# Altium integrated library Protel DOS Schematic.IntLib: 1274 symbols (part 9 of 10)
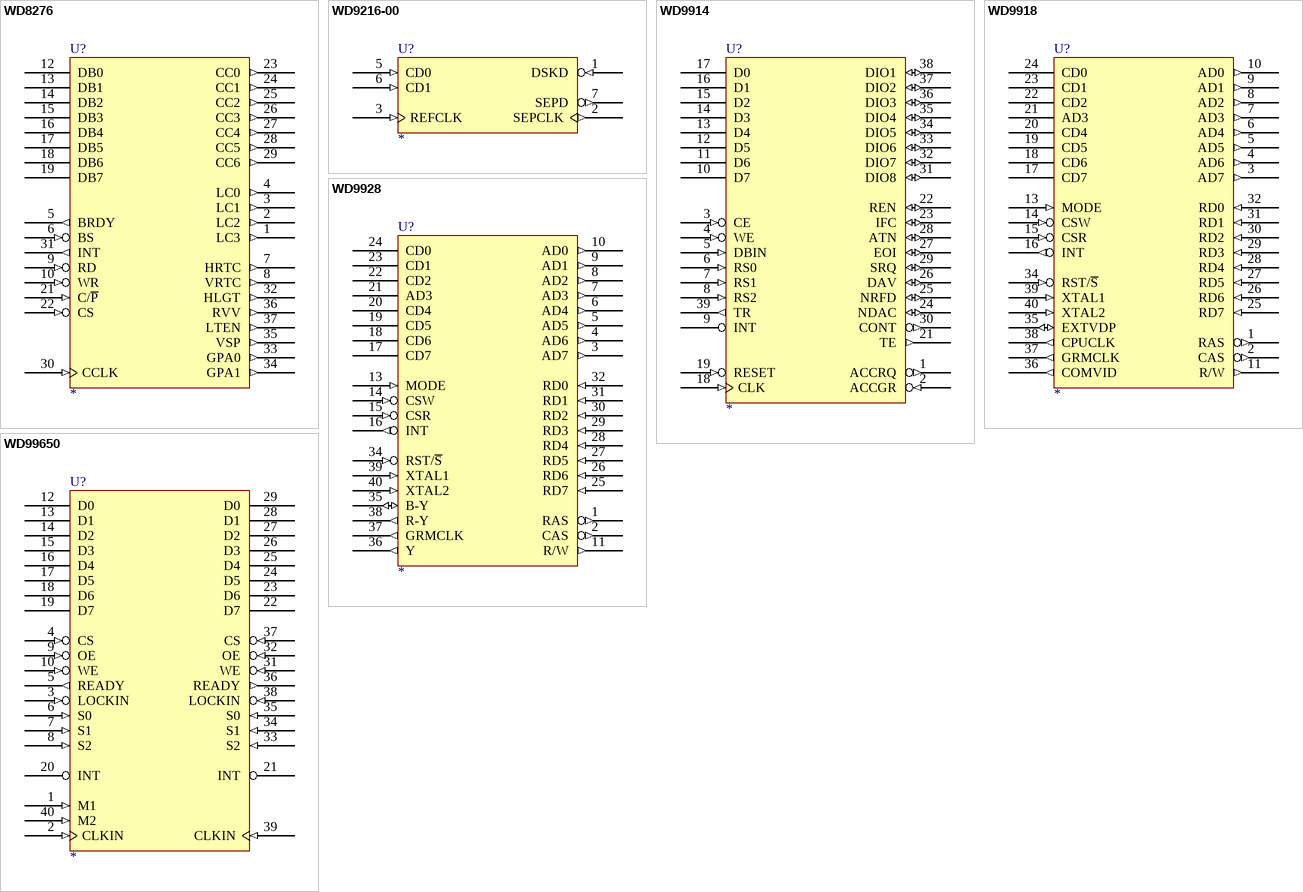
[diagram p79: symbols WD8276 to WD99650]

## WD9928
designator U?
footprint DIP-40
pins: 1 RAS (out), 2 CAS (out), 3 AD7 (out), 4 AD6 (out), 5 AD5 (out), 6 AD4 (out), 7 AD3 (out), 8 AD2 (out), 9 AD1 (out), 10 AD0 (out), 11 R/W (out), 12 GND (power) hidden to GND, 13 MODE (in), 14 CSW (in), 15 CSR (in), 16 INT (out), 17 CD7 (hiz), 18 CD6 (hiz), 19 CD5 (hiz), 20 CD4 (hiz), 21 AD3 (hiz), 22 CD2 (hiz), 23 CD1 (hiz), 24 CD0 (hiz), 25 RD7 (in), 26 RD6 (in), 27 RD5 (in), 28 RD4 (in), 29 RD3 (in), 30 RD2 (in), 31 RD1 (in), 32 RD0 (in), 33 VCC (power) hidden to VCC, 34 RST/~{S} (in), 35 B-Y (io), 36 Y (out), 37 GRMCLK (out), 38 R-Y (out), 39 XTAL1 (in), 40 XTAL2 (in)
2 alternate drawings of the same symbol

## WD99650
designator U?
footprint DIP-40
pins: 1 M1 (in), 2 CLKIN (in), 3 LOCKIN (in), 4 CS (in), 5 READY (out), 6 S0 (in), 7 S1 (in), 8 S2 (in), 9 OE (in), 10 WE (in), 11 GND (power) hidden to GND, 12 D0 (hiz), 13 D1 (hiz), 14 D2 (hiz), 15 D3 (hiz), 16 D4 (hiz), 17 D5 (hiz), 18 D6 (hiz), 19 D7 (hiz), 20 INT (oc), 21 INT (oc), 22 D7 (hiz), 23 D6 (hiz), 24 D5 (hiz), 25 D4 (hiz), 26 D3 (hiz), 27 D2 (hiz), 28 D1 (hiz), 29 D0 (hiz), 30 VCC (power) hidden to VCC, 31 WE (in), 32 OE (in), 33 S2 (in), 34 S1 (in), 35 S0 (in), 36 READY (out), 37 CS (in), 38 LOCKIN (in), 39 CLKIN (in), 40 M2 (in)
2 alternate drawings of the same symbol


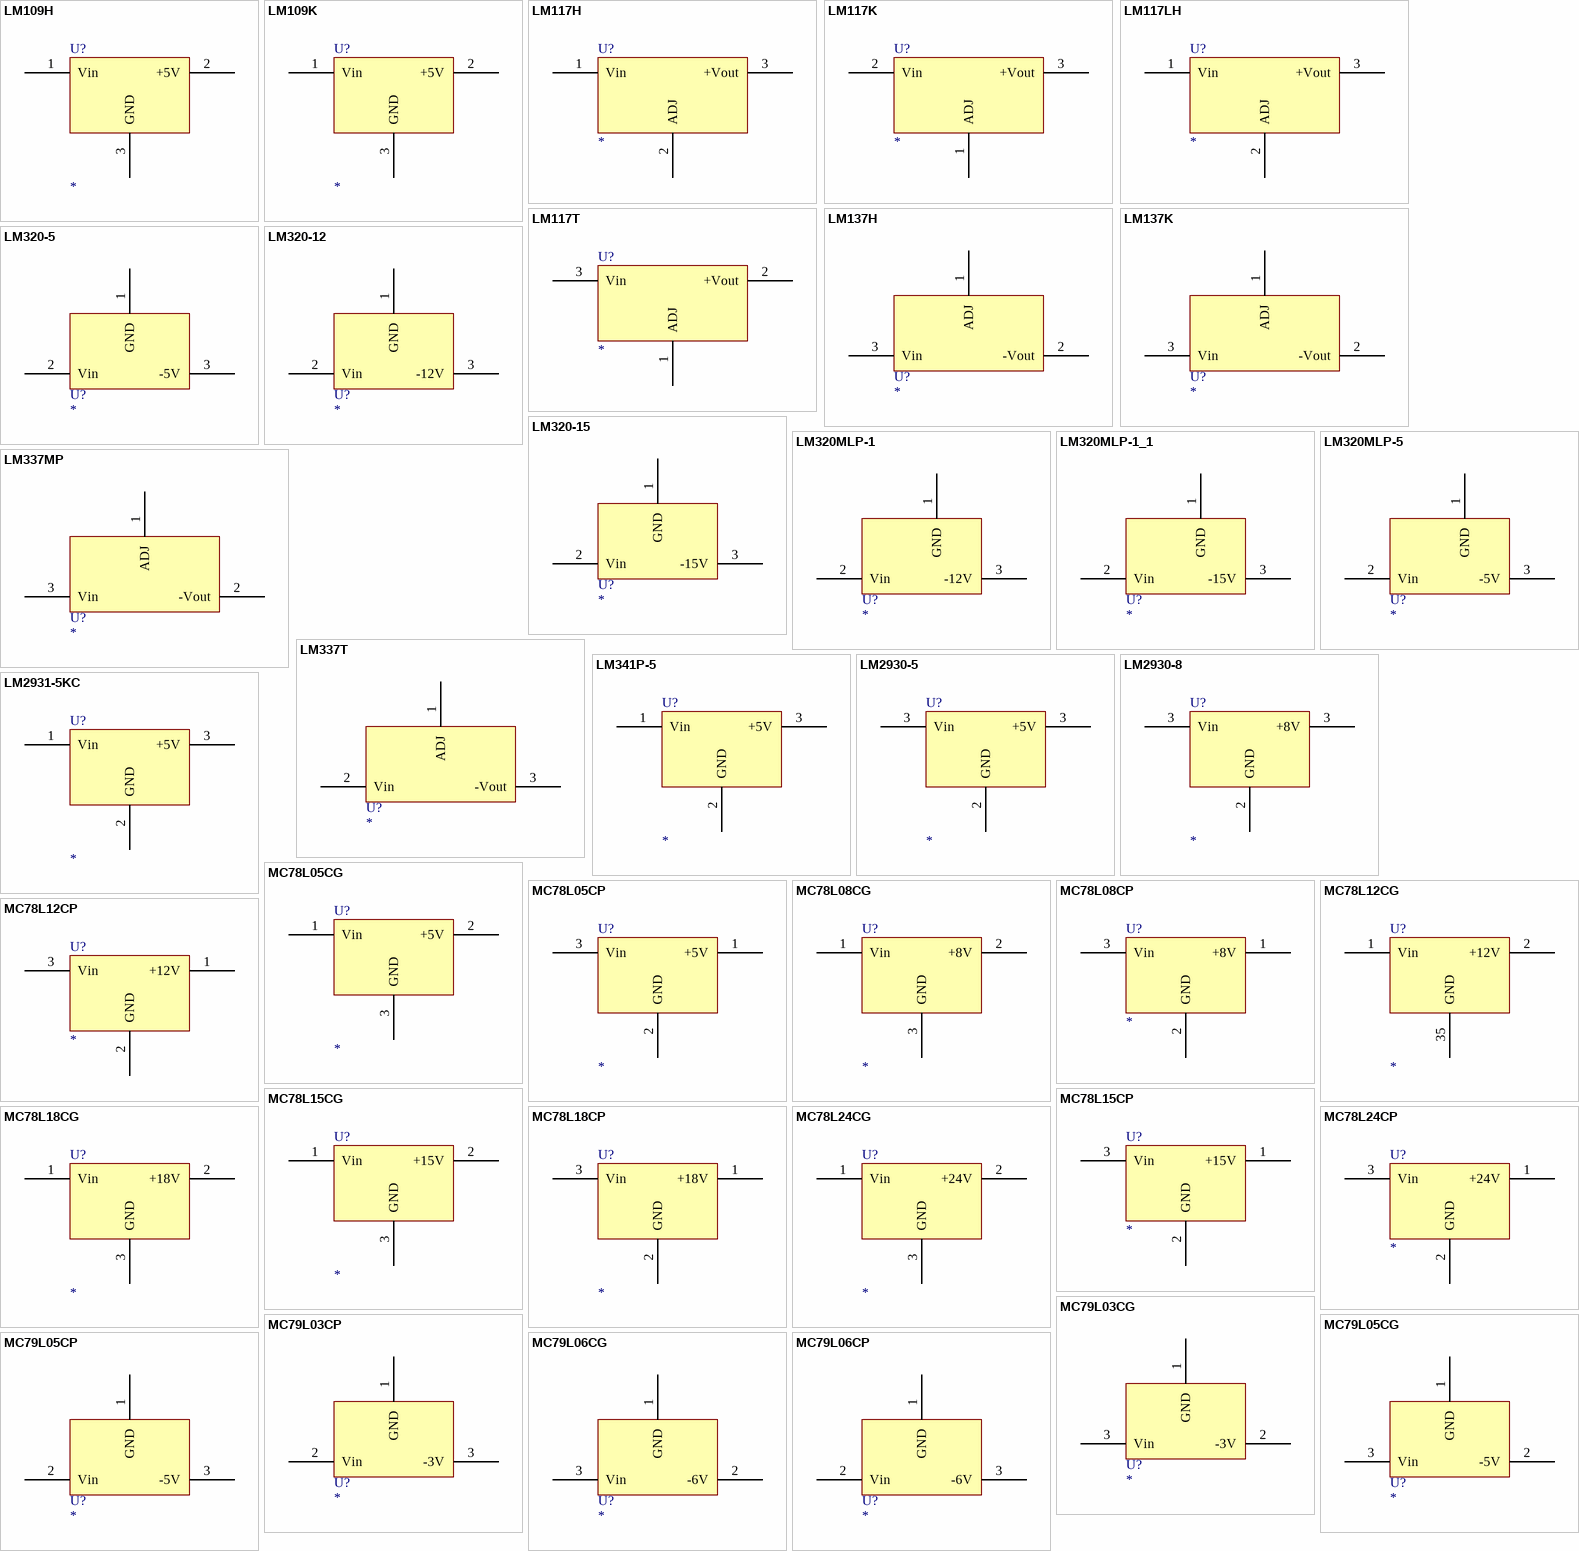
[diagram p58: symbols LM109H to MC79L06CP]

## LM109H
designator U?
footprint TO-39
pins: 1 Vin, 2 +5V, 3 GND
2 alternate drawings of the same symbol

## LM109K
designator U?
footprint TO-3
pins: 1 Vin, 2 +5V, 3 GND
2 alternate drawings of the same symbol

## LM117H
designator U?
footprint TO39
pins: 1 Vin, 2 ADJ, 3 +Vout
2 alternate drawings of the same symbol

## LM117K
designator U?
footprint TO3
footprint TO220V
footprint TO220H
footprint TO252-3L (Footprint not found)
pins: 1 ADJ, 2 Vin, 3 +Vout
2 alternate drawings of the same symbol

## LM117LH
designator U?
footprint TO39
pins: 1 Vin, 2 ADJ, 3 +Vout
2 alternate drawings of the same symbol

## LM117T
designator U?
footprint TO220H
footprint TO220V
footprint TO252-3L (Footprint not found)
pins: 1 ADJ, 2 +Vout, 3 Vin
2 alternate drawings of the same symbol

## LM137H
designator U?
footprint TO-39
pins: 1 ADJ, 2 -Vout, 3 Vin
2 alternate drawings of the same symbol

## LM137K
designator U?
footprint TO-3
pins: 1 ADJ, 2 -Vout, 3 Vin
2 alternate drawings of the same symbol

## LM320-5
designator U?
footprint TO220H
pins: 1 GND, 2 Vin, 3 -5V
2 alternate drawings of the same symbol

## LM320-12
designator U?
footprint TO220H
pins: 1 GND, 2 Vin, 3 -12V
2 alternate drawings of the same symbol

## LM320-15
designator U?
footprint TO220H
pins: 1 GND, 2 Vin, 3 -15V
2 alternate drawings of the same symbol

## LM320MLP-1
designator U?
footprint TO202H
pins: 1 GND, 2 Vin, 3 -12V
2 alternate drawings of the same symbol

## LM320MLP-1_1
designator U?
footprint TO202H
pins: 1 GND, 2 Vin, 3 -15V
2 alternate drawings of the same symbol

## LM320MLP-5
designator U?
footprint TO202H
pins: 1 GND, 2 Vin, 3 -5V
2 alternate drawings of the same symbol

## LM337MP
designator U?
footprint TO202H
pins: 1 ADJ, 2 -Vout, 3 Vin
2 alternate drawings of the same symbol

## LM337T
designator U?
footprint TO220H
footprint TO220V
pins: 1 ADJ, 2 Vin, 3 -Vout
2 alternate drawings of the same symbol

## LM341P-5
designator U?
footprint TO202H
pins: 1 Vin, 2 GND, 3 +5V
2 alternate drawings of the same symbol

## LM2930-5
designator U?
footprint TO220H
pins: 2 GND, 3 Vin, 3 +5V
2 alternate drawings of the same symbol

## LM2930-8
designator U?
footprint TO220H
pins: 2 GND, 3 Vin, 3 +8V
2 alternate drawings of the same symbol

## LM2931-5KC
designator U?
footprint TO220H
pins: 1 Vin, 2 GND, 3 +5V
2 alternate drawings of the same symbol

## MC78L05CG
designator U?
footprint TO-39
pins: 1 Vin, 2 +5V, 3 GND
2 alternate drawings of the same symbol

## MC78L05CP
designator U?
footprint TO-92A
pins: 1 +5V, 2 GND, 3 Vin
2 alternate drawings of the same symbol

## MC78L08CG
designator U?
footprint TO-39
pins: 1 Vin, 2 +8V, 3 GND
2 alternate drawings of the same symbol

## MC78L08CP
designator U?
footprint TO-92A
pins: 1 +8V, 2 GND, 3 Vin
2 alternate drawings of the same symbol

## MC78L12CG
designator U?
footprint TO-39
pins: 1 Vin, 2 +12V, 35 GND
2 alternate drawings of the same symbol

## MC78L12CP
designator U?
footprint TO-92A
pins: 1 +12V, 2 GND, 3 Vin
2 alternate drawings of the same symbol

## MC78L15CG
designator U?
footprint TO-39
pins: 1 Vin, 2 +15V, 3 GND
2 alternate drawings of the same symbol

## MC78L15CP
designator U?
footprint TO-92A
pins: 1 +15V, 2 GND, 3 Vin
2 alternate drawings of the same symbol

## MC78L18CG
designator U?
footprint TO-39
pins: 1 Vin, 2 +18V, 3 GND
2 alternate drawings of the same symbol

## MC78L18CP
designator U?
footprint TO-92A
pins: 1 +18V, 2 GND, 3 Vin
2 alternate drawings of the same symbol

## MC78L24CG
designator U?
footprint TO-39
pins: 1 Vin, 2 +24V, 3 GND
2 alternate drawings of the same symbol

## MC78L24CP
designator U?
footprint TO-92A
pins: 1 +24V, 2 GND, 3 Vin
2 alternate drawings of the same symbol

## MC79L03CG
designator U?
footprint TO-39
pins: 1 GND, 2 -3V, 3 Vin
2 alternate drawings of the same symbol

## MC79L03CP
designator U?
footprint TO-92A
pins: 1 GND, 2 Vin, 3 -3V
2 alternate drawings of the same symbol

## MC79L05CG
designator U?
footprint TO-39
pins: 1 GND, 2 -5V, 3 Vin
2 alternate drawings of the same symbol

## MC79L05CP
designator U?
footprint TO-92A
pins: 1 GND, 2 Vin, 3 -5V
2 alternate drawings of the same symbol

## MC79L06CG
designator U?
footprint TO-39
pins: 1 GND, 2 -6V, 3 Vin
2 alternate drawings of the same symbol

## MC79L06CP
designator U?
footprint TO-92A
pins: 1 GND, 2 Vin, 3 -6V
2 alternate drawings of the same symbol

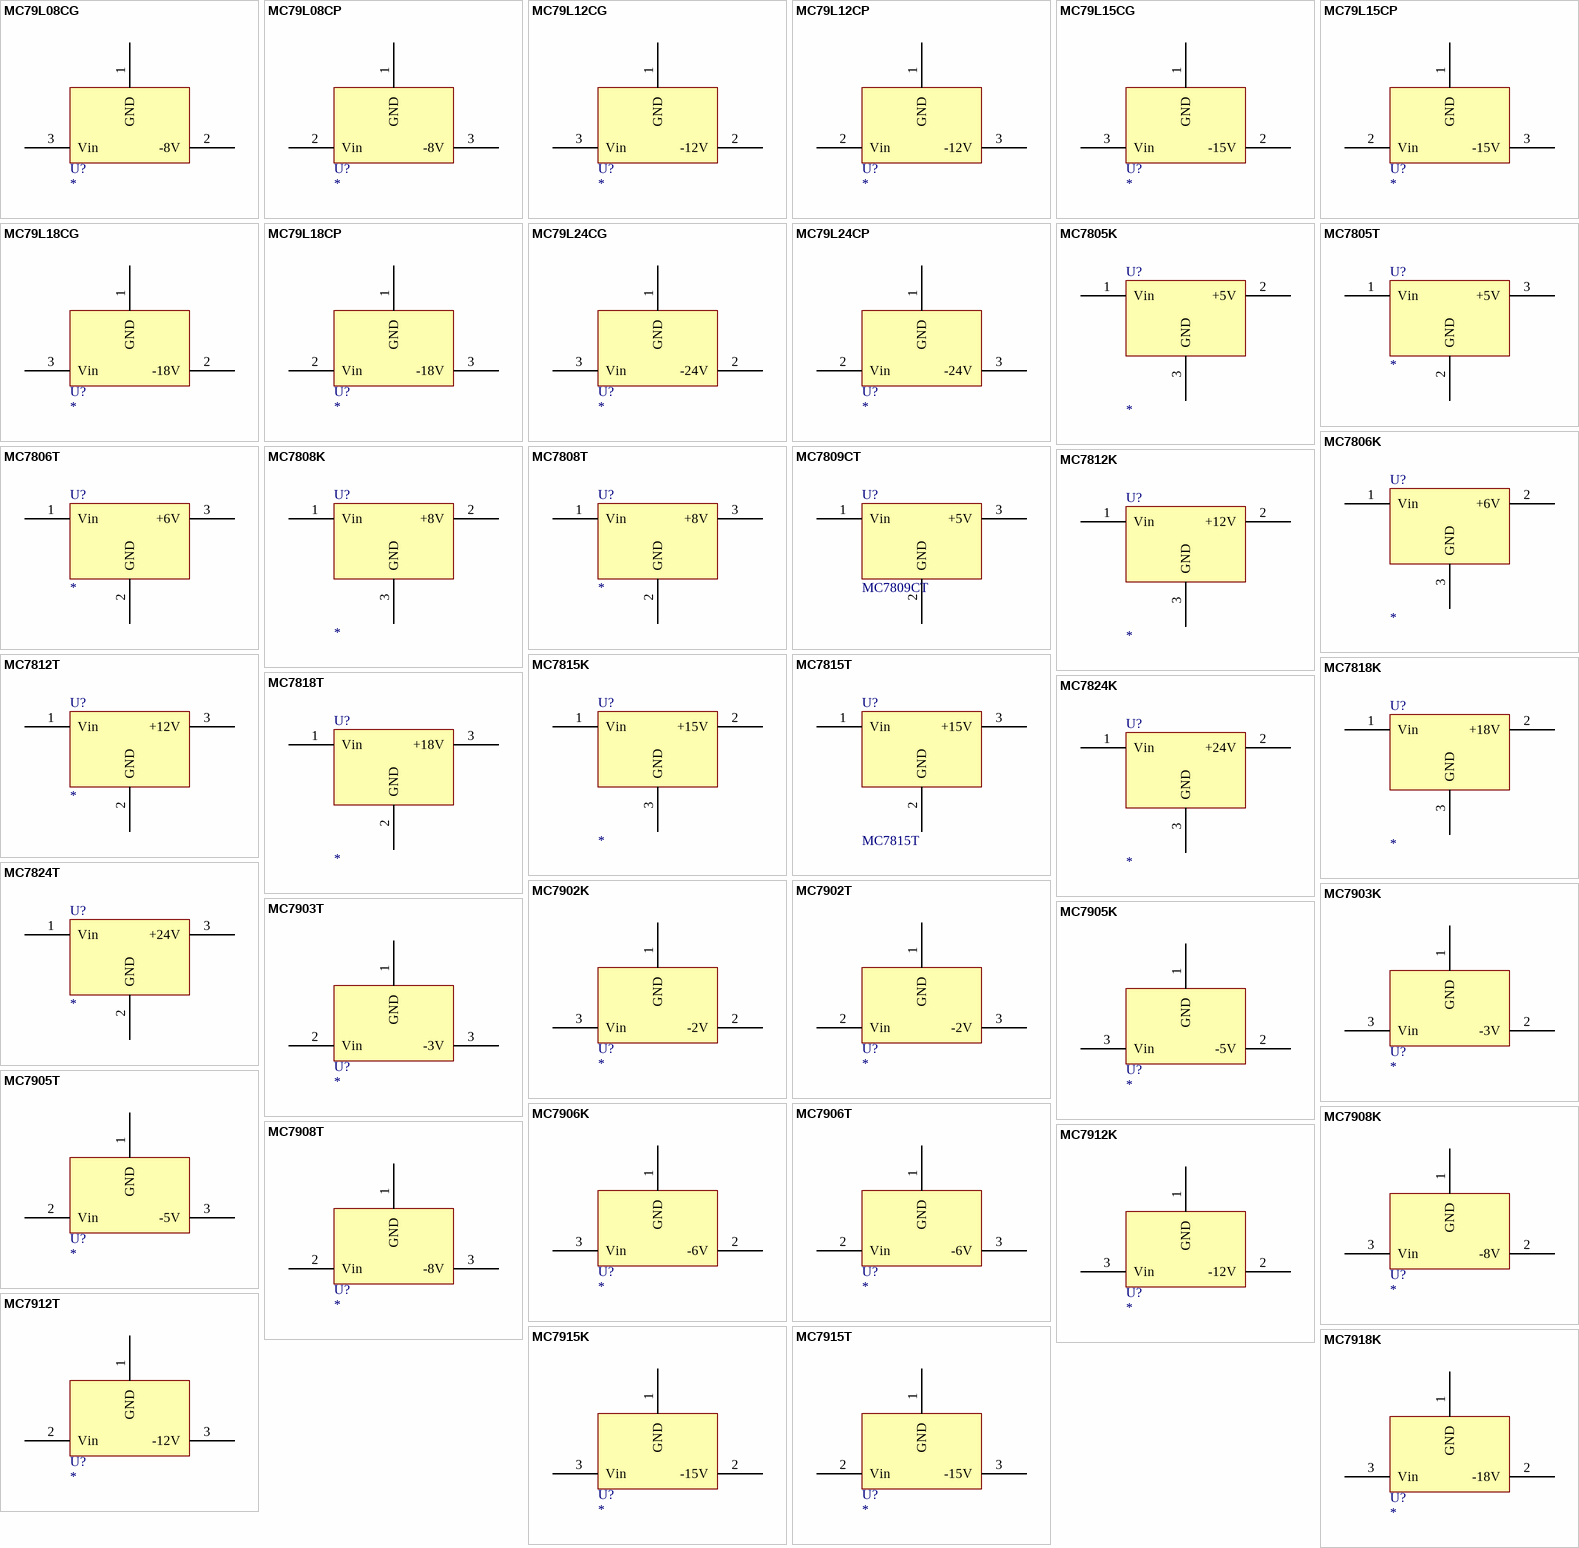
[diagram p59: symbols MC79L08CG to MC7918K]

## MC79L08CG
designator U?
footprint TO-39
pins: 1 GND, 2 -8V, 3 Vin
2 alternate drawings of the same symbol

## MC79L08CP
designator U?
footprint TO-92A
pins: 1 GND, 2 Vin, 3 -8V
2 alternate drawings of the same symbol

## MC79L12CG
designator U?
footprint TO-39
pins: 1 GND, 2 -12V, 3 Vin
2 alternate drawings of the same symbol

## MC79L12CP
designator U?
footprint TO-92A
pins: 1 GND, 2 Vin, 3 -12V
2 alternate drawings of the same symbol

## MC79L15CG
designator U?
footprint TO-39
pins: 1 GND, 2 -15V, 3 Vin
2 alternate drawings of the same symbol

## MC79L15CP
designator U?
footprint TO-92A
pins: 1 GND, 2 Vin, 3 -15V
2 alternate drawings of the same symbol

## MC79L18CG
designator U?
footprint TO-39
pins: 1 GND, 2 -18V, 3 Vin
2 alternate drawings of the same symbol

## MC79L18CP
designator U?
footprint TO-92A
pins: 1 GND, 2 Vin, 3 -18V
2 alternate drawings of the same symbol

## MC79L24CG
designator U?
footprint TO-39
pins: 1 GND, 2 -24V, 3 Vin
2 alternate drawings of the same symbol

## MC79L24CP
designator U?
footprint TO-92A
pins: 1 GND, 2 Vin, 3 -24V
2 alternate drawings of the same symbol

## MC7805K
designator U?
footprint TO-3
pins: 1 Vin, 2 +5V, 3 GND
2 alternate drawings of the same symbol

## MC7805T
designator U?
footprint TO220H
footprint TO220V
footprint TO257H
pins: 1 Vin, 2 GND, 3 +5V
2 alternate drawings of the same symbol

## MC7806K
designator U?
footprint TO-3
pins: 1 Vin, 2 +6V, 3 GND
2 alternate drawings of the same symbol

## MC7806T
designator U?
footprint TO220H
footprint TO220V
pins: 1 Vin, 2 GND, 3 +6V
2 alternate drawings of the same symbol

## MC7808K
designator U?
footprint TO-3
pins: 1 Vin, 2 +8V, 3 GND
2 alternate drawings of the same symbol

## MC7808T
designator U?
footprint TO220H
footprint TO220V
pins: 1 Vin, 2 GND, 3 +8V
2 alternate drawings of the same symbol

## MC7809CT
designator U?
footprint TO220H
footprint TO220V
footprint TO257H
pins: 1 Vin, 2 GND, 3 +5V
2 alternate drawings of the same symbol

## MC7812K
designator U?
footprint TO-3
pins: 1 Vin, 2 +12V, 3 GND
2 alternate drawings of the same symbol

## MC7812T
designator U?
footprint TO220H
footprint TO220V
pins: 1 Vin, 2 GND, 3 +12V
2 alternate drawings of the same symbol

## MC7815K
designator U?
footprint TO-3
pins: 1 Vin, 2 +15V, 3 GND
2 alternate drawings of the same symbol

## MC7815T
designator U?
footprint TO220H
footprint TO220V
pins: 1 Vin, 2 GND, 3 +15V
2 alternate drawings of the same symbol

## MC7818K
designator U?
footprint TO-3
pins: 1 Vin, 2 +18V, 3 GND
2 alternate drawings of the same symbol

## MC7818T
designator U?
footprint TO220H
pins: 1 Vin, 2 GND, 3 +18V
2 alternate drawings of the same symbol

## MC7824K
designator U?
footprint TO-3
pins: 1 Vin, 2 +24V, 3 GND
2 alternate drawings of the same symbol

## MC7824T
designator U?
footprint TO220H
footprint TO220V
pins: 1 Vin, 2 GND, 3 +24V
2 alternate drawings of the same symbol

## MC7902K
designator U?
footprint TO-3
pins: 1 GND, 2 -2V, 3 Vin
2 alternate drawings of the same symbol

## MC7902T
designator U?
footprint TO220H
pins: 1 GND, 2 Vin, 3 -2V
2 alternate drawings of the same symbol

## MC7903K
designator U?
footprint TO-3
pins: 1 GND, 2 -3V, 3 Vin
2 alternate drawings of the same symbol

## MC7903T
designator U?
footprint TO220H
pins: 1 GND, 2 Vin, 3 -3V
2 alternate drawings of the same symbol

## MC7905K
designator U?
footprint TO-3
pins: 1 GND, 2 -5V, 3 Vin
2 alternate drawings of the same symbol

## MC7905T
designator U?
footprint TO220H
footprint TO220V
pins: 1 GND, 2 Vin, 3 -5V
2 alternate drawings of the same symbol

## MC7906K
designator U?
footprint TO-3
pins: 1 GND, 2 -6V, 3 Vin
2 alternate drawings of the same symbol

## MC7906T
designator U?
footprint TO220H
footprint TO220V
pins: 1 GND, 2 Vin, 3 -6V
2 alternate drawings of the same symbol

## MC7908K
designator U?
footprint TO-3
pins: 1 GND, 2 -8V, 3 Vin
2 alternate drawings of the same symbol

## MC7908T
designator U?
footprint TO220H
footprint TO220V
pins: 1 GND, 2 Vin, 3 -8V
2 alternate drawings of the same symbol

## MC7912K
designator U?
footprint TO-3
pins: 1 GND, 2 -12V, 3 Vin
2 alternate drawings of the same symbol

## MC7912T
designator U?
footprint TO220H
footprint TO220V
pins: 1 GND, 2 Vin, 3 -12V
2 alternate drawings of the same symbol

## MC7915K
designator U?
footprint TO-3
pins: 1 GND, 2 -15V, 3 Vin
2 alternate drawings of the same symbol

## MC7915T
designator U?
footprint TO220H
footprint TO220V
pins: 1 GND, 2 Vin, 3 -15V
2 alternate drawings of the same symbol

## MC7918K
designator U?
footprint TO-3
pins: 1 GND, 2 -18V, 3 Vin
2 alternate drawings of the same symbol

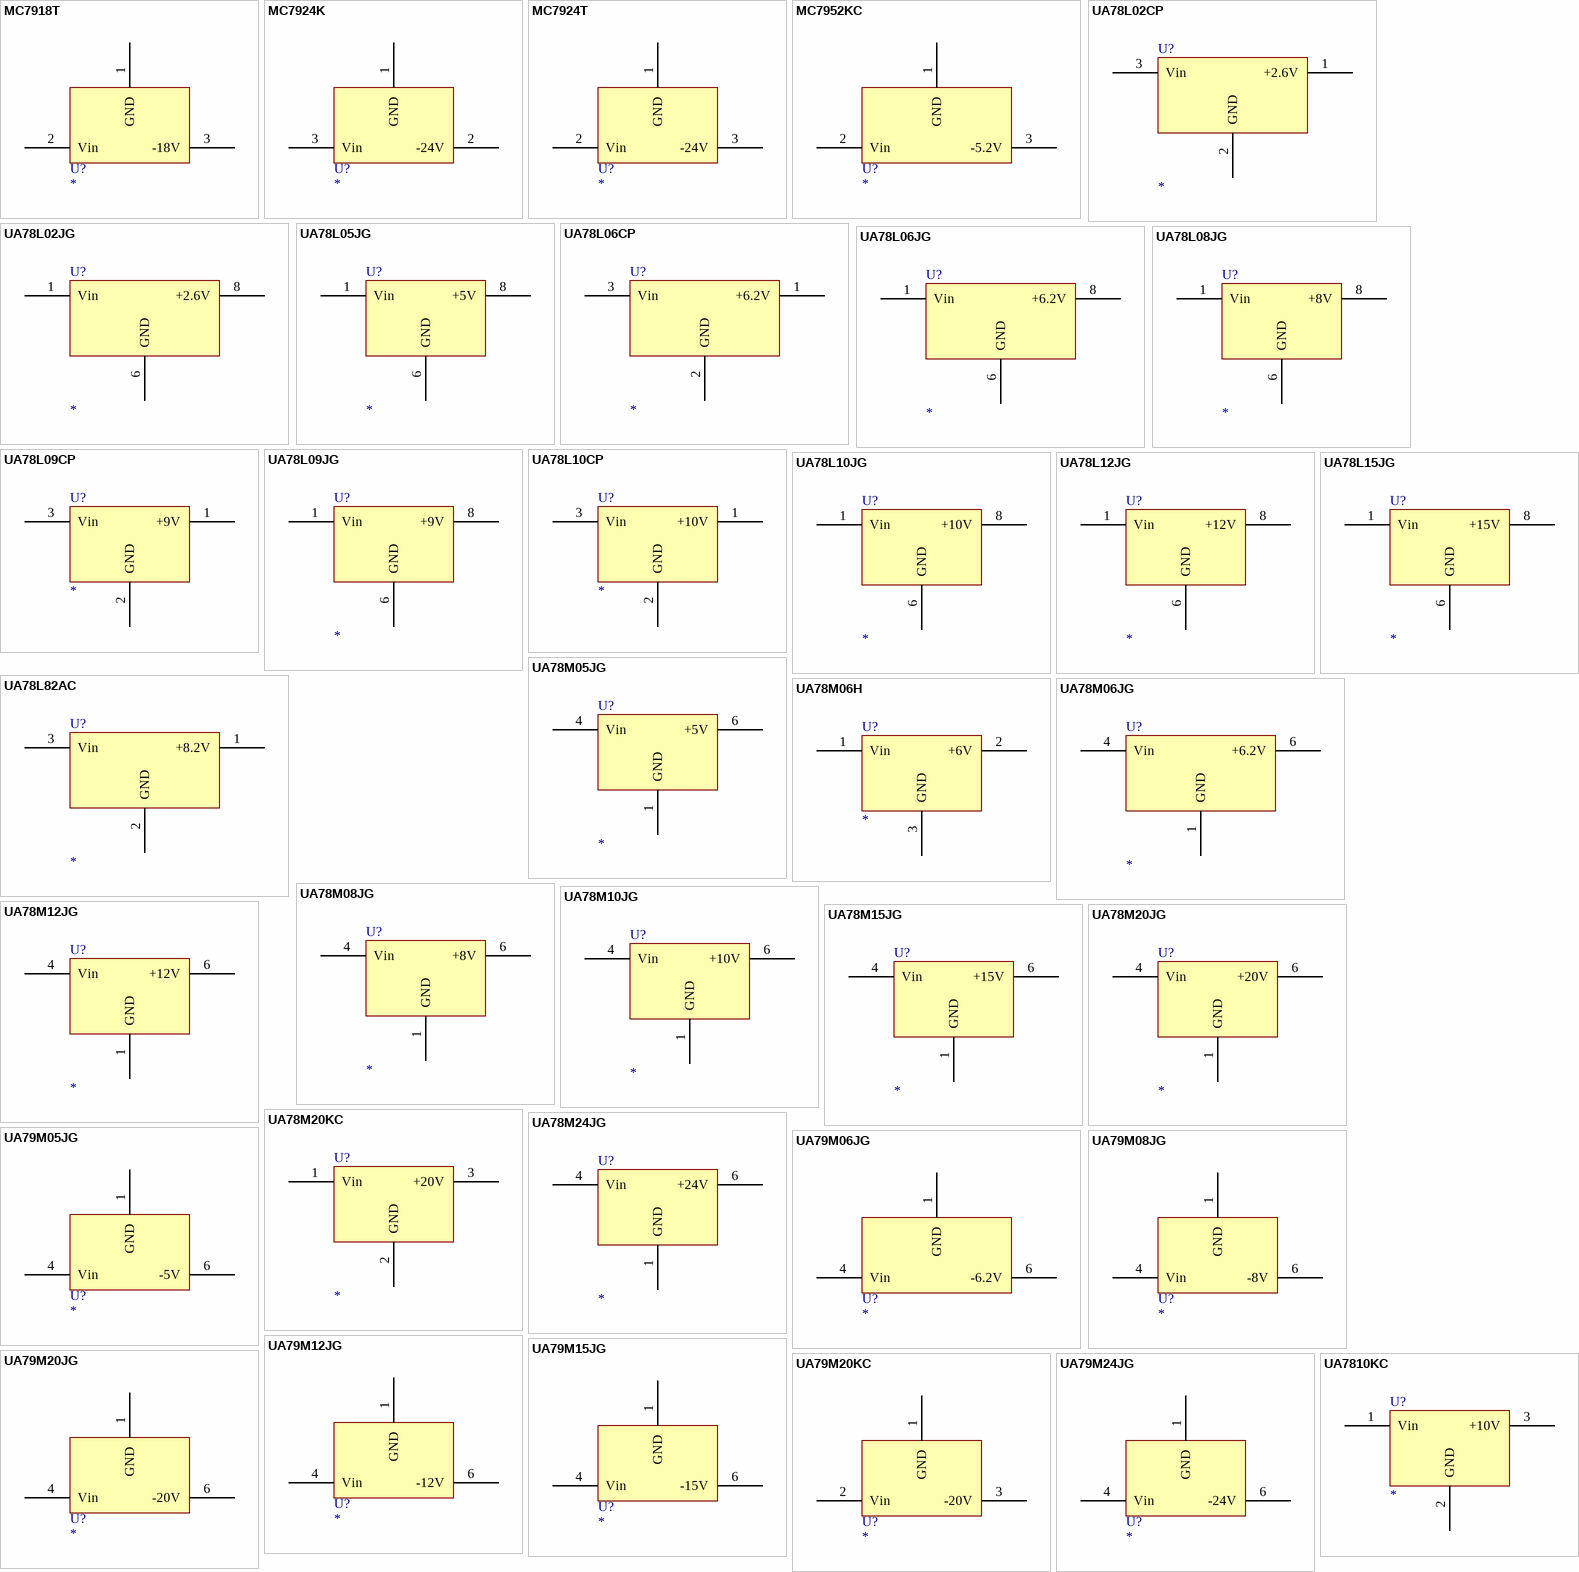
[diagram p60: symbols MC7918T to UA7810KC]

## MC7918T
designator U?
footprint TO220H
pins: 1 GND, 2 Vin, 3 -18V
2 alternate drawings of the same symbol

## MC7924K
designator U?
footprint TO-3
pins: 1 GND, 2 -24V, 3 Vin
2 alternate drawings of the same symbol

## MC7924T
designator U?
footprint TO220H
footprint TO220V
pins: 1 GND, 2 Vin, 3 -24V
2 alternate drawings of the same symbol

## MC7952KC
designator U?
footprint TO220H
pins: 1 GND, 2 Vin, 3 -5.2V
2 alternate drawings of the same symbol

## UA78L02CP
designator U?
footprint TO-92A
pins: 1 +2.6V, 2 GND, 3 Vin
2 alternate drawings of the same symbol

## UA78L02JG
designator U?
footprint DIP-8
pins: 1 Vin, 6 GND, 8 +2.6V
2 alternate drawings of the same symbol

## UA78L05JG
designator U?
footprint DIP-8
pins: 1 Vin, 6 GND, 8 +5V
2 alternate drawings of the same symbol

## UA78L06CP
designator U?
footprint TO-92A
pins: 1 +6.2V, 2 GND, 3 Vin
2 alternate drawings of the same symbol

## UA78L06JG
designator U?
footprint DIP-8
pins: 1 Vin, 6 GND, 8 +6.2V
2 alternate drawings of the same symbol

## UA78L08JG
designator U?
footprint DIP-8
pins: 1 Vin, 6 GND, 8 +8V
2 alternate drawings of the same symbol

## UA78L09CP
designator U?
footprint TO-92A
pins: 1 +9V, 2 GND, 3 Vin
2 alternate drawings of the same symbol

## UA78L09JG
designator U?
footprint DIP-8
pins: 1 Vin, 6 GND, 8 +9V
2 alternate drawings of the same symbol

## UA78L10CP
designator U?
footprint TO-92A
pins: 1 +10V, 2 GND, 3 Vin
2 alternate drawings of the same symbol

## UA78L10JG
designator U?
footprint DIP-8
pins: 1 Vin, 6 GND, 8 +10V
2 alternate drawings of the same symbol

## UA78L12JG
designator U?
footprint DIP-8
pins: 1 Vin, 6 GND, 8 +12V
2 alternate drawings of the same symbol

## UA78L15JG
designator U?
footprint DIP-8
pins: 1 Vin, 6 GND, 8 +15V
2 alternate drawings of the same symbol

## UA78L82AC
designator U?
footprint TO-92A
pins: 1 +8.2V, 2 GND, 3 Vin
2 alternate drawings of the same symbol

## UA78M05JG
designator U?
footprint DIP-8
pins: 1 GND, 4 Vin, 6 +5V
2 alternate drawings of the same symbol

## UA78M06H
designator U?
footprint TO-39
pins: 1 Vin, 2 +6V, 3 GND
2 alternate drawings of the same symbol

## UA78M06JG
designator U?
footprint DIP-8
pins: 1 GND, 4 Vin, 6 +6.2V
2 alternate drawings of the same symbol

## UA78M08JG
designator U?
footprint DIP-8
pins: 1 GND, 4 Vin, 6 +8V
2 alternate drawings of the same symbol

## UA78M10JG
designator U?
footprint DIP-8
pins: 1 GND, 4 Vin, 6 +10V
2 alternate drawings of the same symbol

## UA78M12JG
designator U?
footprint DIP-8
pins: 1 GND, 4 Vin, 6 +12V
2 alternate drawings of the same symbol

## UA78M15JG
designator U?
footprint DIP-8
pins: 1 GND, 4 Vin, 6 +15V
2 alternate drawings of the same symbol

## UA78M20JG
designator U?
footprint DIP-8
pins: 1 GND, 4 Vin, 6 +20V
2 alternate drawings of the same symbol

## UA78M20KC
designator U?
footprint TO220H
pins: 1 Vin, 2 GND, 3 +20V
2 alternate drawings of the same symbol

## UA78M24JG
designator U?
footprint DIP-8
pins: 1 GND, 4 Vin, 6 +24V
2 alternate drawings of the same symbol

## UA79M05JG
designator U?
footprint DIP-8
pins: 1 GND, 4 Vin, 6 -5V
2 alternate drawings of the same symbol

## UA79M06JG
designator U?
footprint DIP-8
pins: 1 GND, 4 Vin, 6 -6.2V
2 alternate drawings of the same symbol

## UA79M08JG
designator U?
footprint DIP-8
pins: 1 GND, 4 Vin, 6 -8V
2 alternate drawings of the same symbol

## UA79M12JG
designator U?
footprint DIP-8
pins: 1 GND, 4 Vin, 6 -12V
2 alternate drawings of the same symbol

## UA79M15JG
designator U?
footprint DIP-8
pins: 1 GND, 4 Vin, 6 -15V
2 alternate drawings of the same symbol

## UA79M20JG
designator U?
footprint DIP-8
pins: 1 GND, 4 Vin, 6 -20V
2 alternate drawings of the same symbol

## UA79M20KC
designator U?
footprint TO220H
pins: 1 GND, 2 Vin, 3 -20V
2 alternate drawings of the same symbol

## UA79M24JG
designator U?
footprint DIP-8
pins: 1 GND, 4 Vin, 6 -24V
2 alternate drawings of the same symbol

## UA7810KC
designator U?
footprint TO220H
footprint TO220V
pins: 1 Vin, 2 GND, 3 +10V
2 alternate drawings of the same symbol

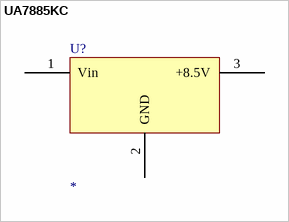
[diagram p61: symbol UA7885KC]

## UA7885KC
designator U?
footprint TO220H
pins: 1 Vin, 2 GND, 3 +8.5V
2 alternate drawings of the same symbol


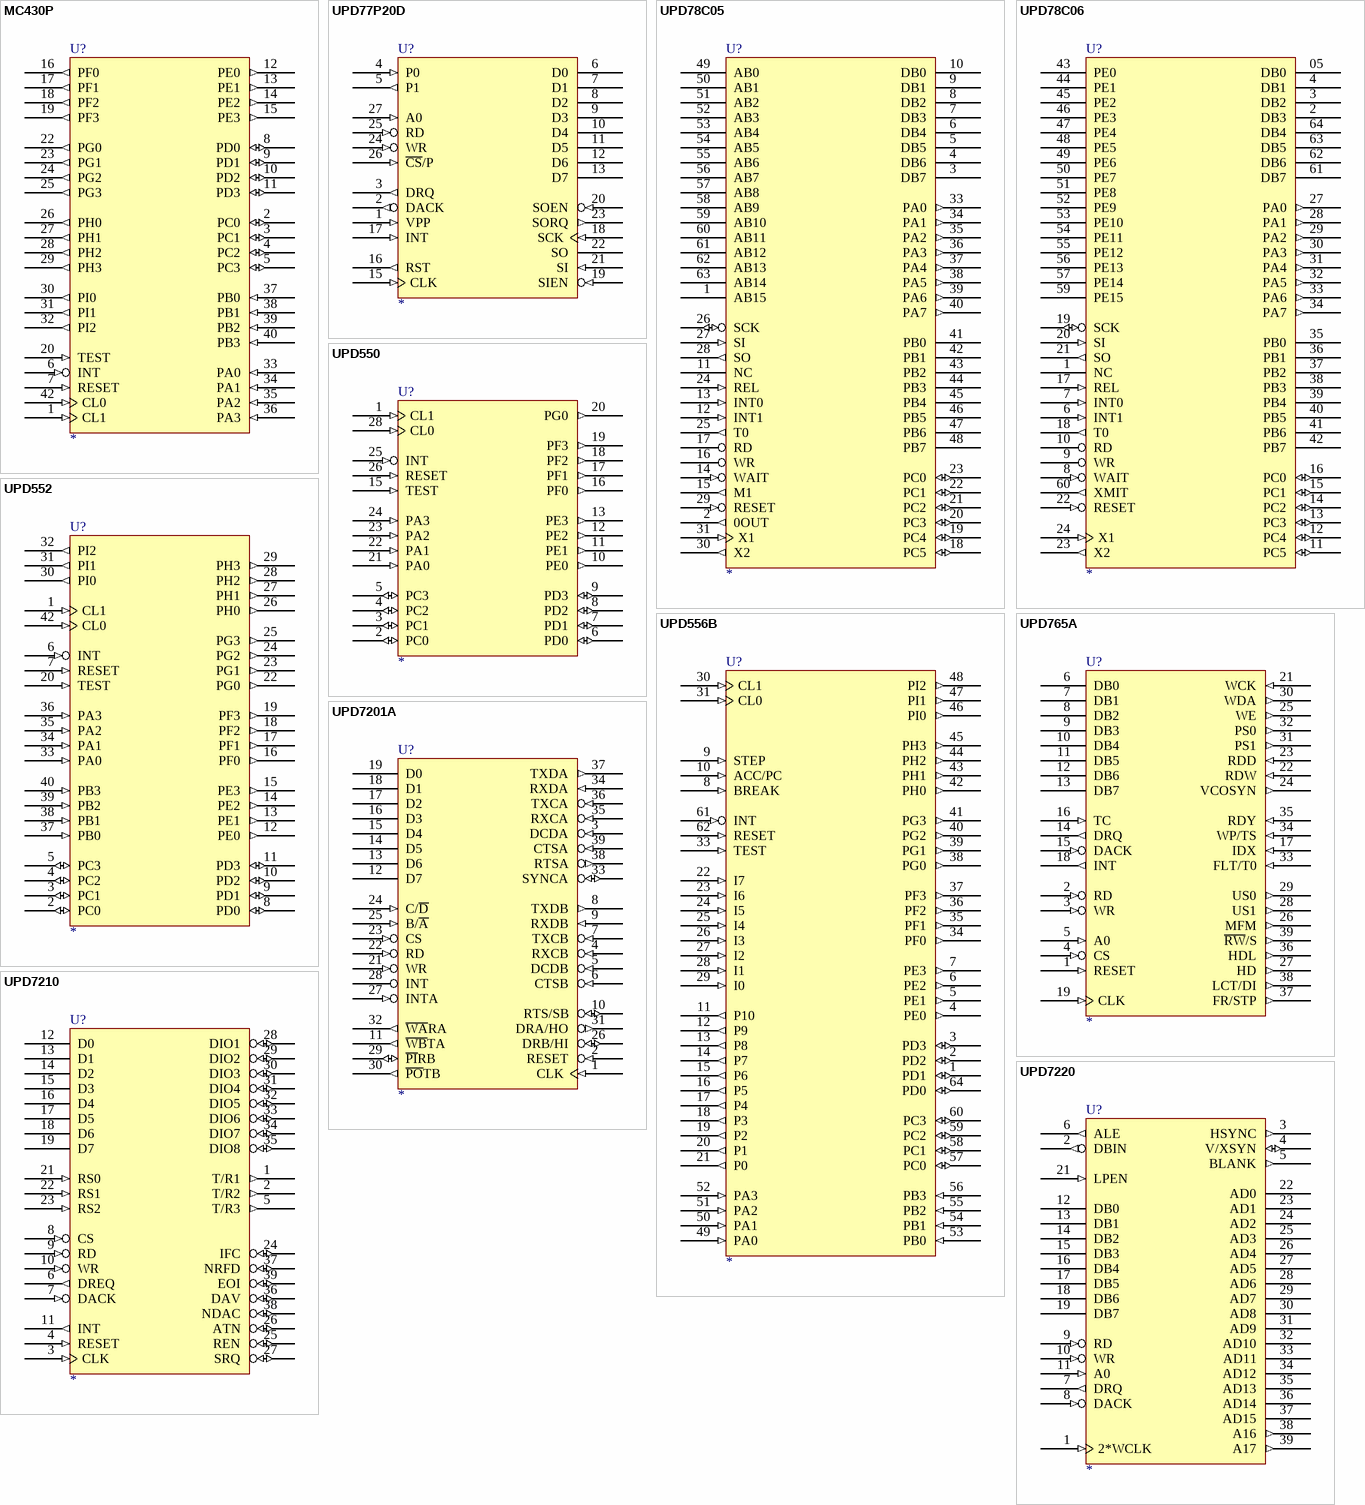
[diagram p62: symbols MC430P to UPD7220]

## MC430P
designator U?
footprint DIP42
pins: 1 CL1 (in), 2 PC0 (io), 3 PC1 (io), 4 PC2 (io), 5 PC3 (io), 6 INT (in), 7 RESET (in), 8 PD0 (io), 9 PD1 (io), 10 PD2 (io), 11 PD3 (io), 12 PE0 (out), 13 PE1 (out), 14 PE2 (out), 15 PE3 (out), 16 PF0 (out), 17 PF1 (out), 18 PF2 (out), 19 PF3 (out), 20 TEST (in), 21 VCC (power) hidden to VCC, 22 PG0 (out), 23 PG1 (out), 24 PG2 (out), 25 PG3 (out), 26 PH0 (out), 27 PH1 (out), 28 PH2 (out), 29 PH3 (out), 30 PI0 (out), 31 PI1 (out), 32 PI2 (out), 33 PA0 (in), 34 PA1 (in), 35 PA2 (in), 36 PA3 (in), 37 PB0 (in), 38 PB1 (in), 39 PB2 (in), 40 PB3 (in), 41 GND (power) hidden to GND, 42 CL0 (in)
2 alternate drawings of the same symbol

## UPD77P20D
designator U?
footprint DIP-28
pins: 1 VPP (in), 2 DACK (out), 3 DRQ (out), 4 P0 (in), 5 P1 (out), 6 D0 (hiz), 7 D1 (hiz), 8 D2 (hiz), 9 D3 (hiz), 10 D4 (hiz), 11 D5 (hiz), 12 D6 (hiz), 13 D7 (hiz), 14 GND (power) hidden to GND, 15 CLK (in), 16 RST (out), 17 INT (in), 18 SCK (in), 19 SIEN (in), 20 SOEN (in), 21 SI (in), 22 SO (hiz), 23 SORQ (out), 24 WR (in), 25 RD (in), 26 ~{CS}/P (in), 27 A0 (in), 28 VCC (power) hidden to VCC
2 alternate drawings of the same symbol

## UPD78C05
designator U?
footprint QUIL64
pins: 1 AB15 (hiz), 2 0OUT (out), 3 DB7 (hiz), 4 DB6 (hiz), 5 DB5 (hiz), 6 DB4 (hiz), 7 DB3 (hiz), 8 DB2 (hiz), 9 DB1 (hiz), 10 DB0 (hiz), 11 NC, 12 INT1 (in), 13 INT0 (in), 14 WAIT (in), 15 M1 (out), 16 WR (hiz), 17 RD (hiz), 18 PC5 (io), 19 PC4 (io), 20 PC3 (io), 21 PC2 (io), 22 PC1 (io), 23 PC0 (io), 24 REL (in), 25 T0 (out), 26 SCK (io), 27 SI (in), 28 SO (out), 29 RESET (in), 30 X2 (out), 31 X1 (in), 32 GND (power) hidden to GND, 33 PA0 (out), 34 PA1 (out), 35 PA2 (out), 36 PA3 (out), 37 PA4 (out), 38 PA5 (out), 39 PA6 (out), 40 PA7 (out), 41 PB0 (hiz), 42 PB1 (hiz), 43 PB2 (hiz), 44 PB3 (hiz), 45 PB4 (hiz), 46 PB5 (hiz), 47 PB6 (hiz), 48 PB7 (hiz), 49 AB0 (hiz), 50 AB1 (hiz), 51 AB2 (hiz), 52 AB3 (hiz), 53 AB4 (hiz), 54 AB5 (hiz), 55 AB6 (hiz), 56 AB7 (hiz), 57 AB8 (hiz), 58 AB9 (hiz), 59 AB10 (hiz), 60 AB11 (hiz), 61 AB12 (hiz), 62 AB13 (hiz), 63 AB14 (hiz), 64 VCC (power) hidden to VCC
2 alternate drawings of the same symbol

## UPD78C06
designator U?
footprint QFP-64
pins: 1 NC, 2 DB3 (hiz), 3 DB2 (hiz), 4 DB1 (hiz), 05 DB0 (hiz), 6 INT1 (in), 7 INT0 (in), 8 WAIT (in), 9 WR (hiz), 10 RD (hiz), 11 PC5 (io), 12 PC4 (io), 13 PC3 (io), 14 PC2 (io), 15 PC1 (io), 16 PC0 (io), 17 REL (in), 18 T0 (out), 19 SCK (io), 20 SI (in), 21 SO (out), 22 RESET (in), 23 X2 (out), 24 X1 (in), 25 GND (power) hidden to GND, 26 VCC (power) hidden to VCC, 27 PA0 (out), 28 PA1 (out), 29 PA2 (out), 30 PA3 (out), 31 PA4 (out), 32 PA5 (out), 33 PA6 (out), 34 PA7 (out), 35 PB0 (hiz), 36 PB1 (hiz), 37 PB2 (hiz), 38 PB3 (hiz), 39 PB4 (hiz), 40 PB5 (hiz), 41 PB6 (hiz), 42 PB7 (hiz), 43 PE0 (hiz), 44 PE1 (hiz), 45 PE2 (hiz), 46 PE3 (hiz), 47 PE4 (hiz), 48 PE5 (hiz), 49 PE6 (hiz), 50 PE7 (hiz), 51 PE8 (hiz), 52 PE9 (hiz), 53 PE10 (hiz), 54 PE11 (hiz), 55 PE12 (hiz), 56 PE13 (hiz), 57 PE14 (hiz), 58 VCC (power) hidden to VCC, 59 PE15 (hiz), 60 XMIT (out), 61 DB7 (hiz), 62 DB6 (hiz), 63 DB5 (hiz), 64 DB4 (hiz)
2 alternate drawings of the same symbol

## UPD550
designator U?
footprint DIP-28
pins: 1 CL1 (in), 2 PC0 (io), 3 PC1 (io), 4 PC2 (io), 5 PC3 (io), 6 PD0 (io), 7 PD1 (io), 8 PD2 (io), 9 PD3 (io), 10 PE0 (out), 11 PE1 (out), 12 PE2 (out), 13 PE3 (out), 14 VCC (power) hidden to VCC, 15 TEST (in), 16 PF0 (out), 17 PF1 (out), 18 PF2 (out), 19 PF3 (out), 20 PG0 (out), 21 PA0 (in), 22 PA1 (in), 23 PA2 (in), 24 PA3 (in), 25 INT (in), 26 RESET (in), 27 GND (power) hidden to GND, 28 CL0 (in)
2 alternate drawings of the same symbol

## UPD552
designator U?
footprint DIP42
pins: 1 CL1 (in), 2 PC0 (io), 3 PC1 (io), 4 PC2 (io), 5 PC3 (io), 6 INT (in), 7 RESET (in), 8 PD0 (io), 9 PD1 (io), 10 PD2 (io), 11 PD3 (io), 12 PE0 (out), 13 PE1 (out), 14 PE2 (out), 15 PE3 (out), 16 PF0 (out), 17 PF1 (out), 18 PF2 (out), 19 PF3 (out), 20 TEST (in), 21 VCC (power) hidden to VCC, 22 PG0 (out), 23 PG1 (out), 24 PG2 (out), 25 PG3 (out), 26 PH0 (out), 27 PH1 (out), 28 PH2 (out), 29 PH3 (out), 30 PI0 (out), 31 PI1 (out), 32 PI2 (out), 33 PA0 (in), 34 PA1 (in), 35 PA2 (in), 36 PA3 (in), 37 PB0 (in), 38 PB1 (in), 39 PB2 (in), 40 PB3 (in), 41 GND (power) hidden to GND, 42 CL0 (in)
2 alternate drawings of the same symbol

## UPD556B
designator U?
footprint DIP-64
pins: 1 PD1 (io), 2 PD2 (io), 3 PD3 (io), 4 PE0 (out), 5 PE1 (out), 6 PE2 (out), 7 PE3 (out), 8 BREAK (in), 9 STEP (in), 10 ACC/PC (in), 11 P10 (out), 12 P9 (out), 13 P8 (out), 14 P7 (out), 15 P6 (out), 16 P5 (out), 17 P4 (out), 18 P3 (out), 19 P2 (out), 20 P1 (out), 21 P0 (out), 22 I7 (in), 23 I6 (in), 24 I5 (in), 25 I4 (in), 26 I3 (in), 27 I2 (in), 28 I1 (in), 29 I0 (in), 30 CL1 (in), 31 CL0 (in), 32 VCC (power) hidden to VCC, 33 TEST (in), 34 PF0 (out), 35 PF1 (out), 36 PF2 (out), 37 PF3 (out), 38 PG0 (out), 39 PG1 (out), 40 PG2 (out), 41 PG3 (out), 42 PH0 (out), 43 PH1 (out), 44 PH2 (out), 45 PH3 (out), 46 PI0 (out), 47 PI1 (out), 48 PI2 (out), 49 PA0 (in), 50 PA1 (in), 51 PA2 (in), 52 PA3 (in), 53 PB0 (in), 54 PB1 (in), 55 PB2 (in), 56 PB3 (in), 57 PC0 (io), 58 PC1 (io), 59 PC2 (io), 60 PC3 (io), 61 INT (in), 62 RESET (in), 63 GND (power) hidden to GND, 64 PD0 (io)
2 alternate drawings of the same symbol

## UPD765A
designator U?
footprint DIP-40
pins: 1 RESET (in), 2 RD (in), 3 WR (in), 4 CS (in), 5 A0 (in), 6 DB0 (hiz), 7 DB1 (hiz), 8 DB2 (hiz), 9 DB3 (hiz), 10 DB4 (hiz), 11 DB5 (hiz), 12 DB6 (hiz), 13 DB7 (hiz), 14 DRQ (out), 15 DACK (in), 16 TC (in), 17 IDX (in), 18 INT (out), 19 CLK (in), 20 GND (power) hidden to GND, 21 WCK (in), 22 RDW (in), 23 RDD (in), 24 VCOSYN (out), 25 WE (out), 26 MFM (out), 27 HD (out), 28 US1 (out), 29 US0 (out), 30 WDA (out), 31 PS1 (out), 32 PS0 (out), 33 FLT/T0 (in), 34 WP/TS (in), 35 RDY (in), 36 HDL (out), 37 FR/STP (out), 38 LCT/DI (out), 39 ~{RW}/S (out), 40 VCC (power) hidden to VCC
2 alternate drawings of the same symbol

## UPD7201A
designator U?
footprint DIP-40
pins: 1 CLK (in), 2 RESET (in), 3 DCDA (in), 4 RXCB (in), 5 DCDB (in), 6 CTSB (in), 7 TXCB (in), 8 TXDB (out), 9 RXDB (in), 10 RTS/SB (io), 11 ~{WB}TA (out), 12 D7 (hiz), 13 D6 (hiz), 14 D5 (hiz), 15 D4 (hiz), 16 D3 (hiz), 17 D2 (hiz), 18 D1 (hiz), 19 D0 (hiz), 20 VCC (power) hidden to VCC, 21 WR (in), 22 RD (in), 23 CS (in), 24 C/~{D} (in), 25 B/~{A} (in), 26 DRB/HI (io), 27 INTA (in), 28 INT (oc), 29 ~{PI}RB (io), 30 ~{PO}TB (out), 31 DRA/HO (out), 32 ~{WA}RA (out), 33 SYNCA (io), 34 RXDA (in), 35 RXCA (in), 36 TXCA (in), 37 TXDA (out), 38 RTSA (out), 39 CTSA (in), 40 GND (power) hidden to GND
2 alternate drawings of the same symbol

## UPD7210
designator U?
footprint DIP-40
pins: 1 T/R1 (out), 2 T/R2 (out), 3 CLK (in), 4 RESET (in), 5 T/R3 (out), 6 DREQ (out), 7 DACK (in), 8 CS (in), 9 RD (in), 10 WR (in), 11 INT (out), 12 D0 (hiz), 13 D1 (hiz), 14 D2 (hiz), 15 D3 (hiz), 16 D4 (hiz), 17 D5 (hiz), 18 D6 (hiz), 19 D7 (hiz), 20 GND (power) hidden to GND, 21 RS0 (in), 22 RS1 (in), 23 RS2 (in), 24 IFC (io), 25 REN (io), 26 ATN (io), 27 SRQ (io), 28 DIO1 (io), 29 DIO2 (io), 30 DIO3 (io), 31 DIO4 (io), 32 DIO5 (io), 33 DIO6 (io), 34 DIO7 (io), 35 DIO8 (io), 36 DAV (io), 37 NRFD (io), 38 NDAC (io), 39 EOI (io), 40 VCC (power) hidden to VCC
2 alternate drawings of the same symbol

## UPD7220
designator U?
footprint DIP-40
pins: 1 2*WCLK (in), 2 DBIN (out), 3 HSYNC (out), 4 V/XSYN (io), 5 BLANK (out), 6 ALE (out), 7 DRQ (out), 8 DACK (in), 9 RD (in), 10 WR (in), 11 A0 (in), 12 DB0 (hiz), 13 DB1 (hiz), 14 DB2 (hiz), 15 DB3 (hiz), 16 DB4 (hiz), 17 DB5 (hiz), 18 DB6 (hiz), 19 DB7 (hiz), 20 GND (power) hidden to GND, 21 LPEN (in), 22 AD0 (hiz), 23 AD1 (hiz), 24 AD2 (hiz), 25 AD3 (hiz), 26 AD4 (hiz), 27 AD5 (hiz), 28 AD6 (hiz), 29 AD7 (hiz), 30 AD8 (hiz), 31 AD9 (hiz), 32 AD10 (hiz), 33 AD11 (hiz), 34 AD12 (hiz), 35 AD13 (hiz), 36 AD14 (hiz), 37 AD15 (hiz), 38 A16 (out), 39 A17 (out), 40 VCC (power) hidden to VCC
2 alternate drawings of the same symbol

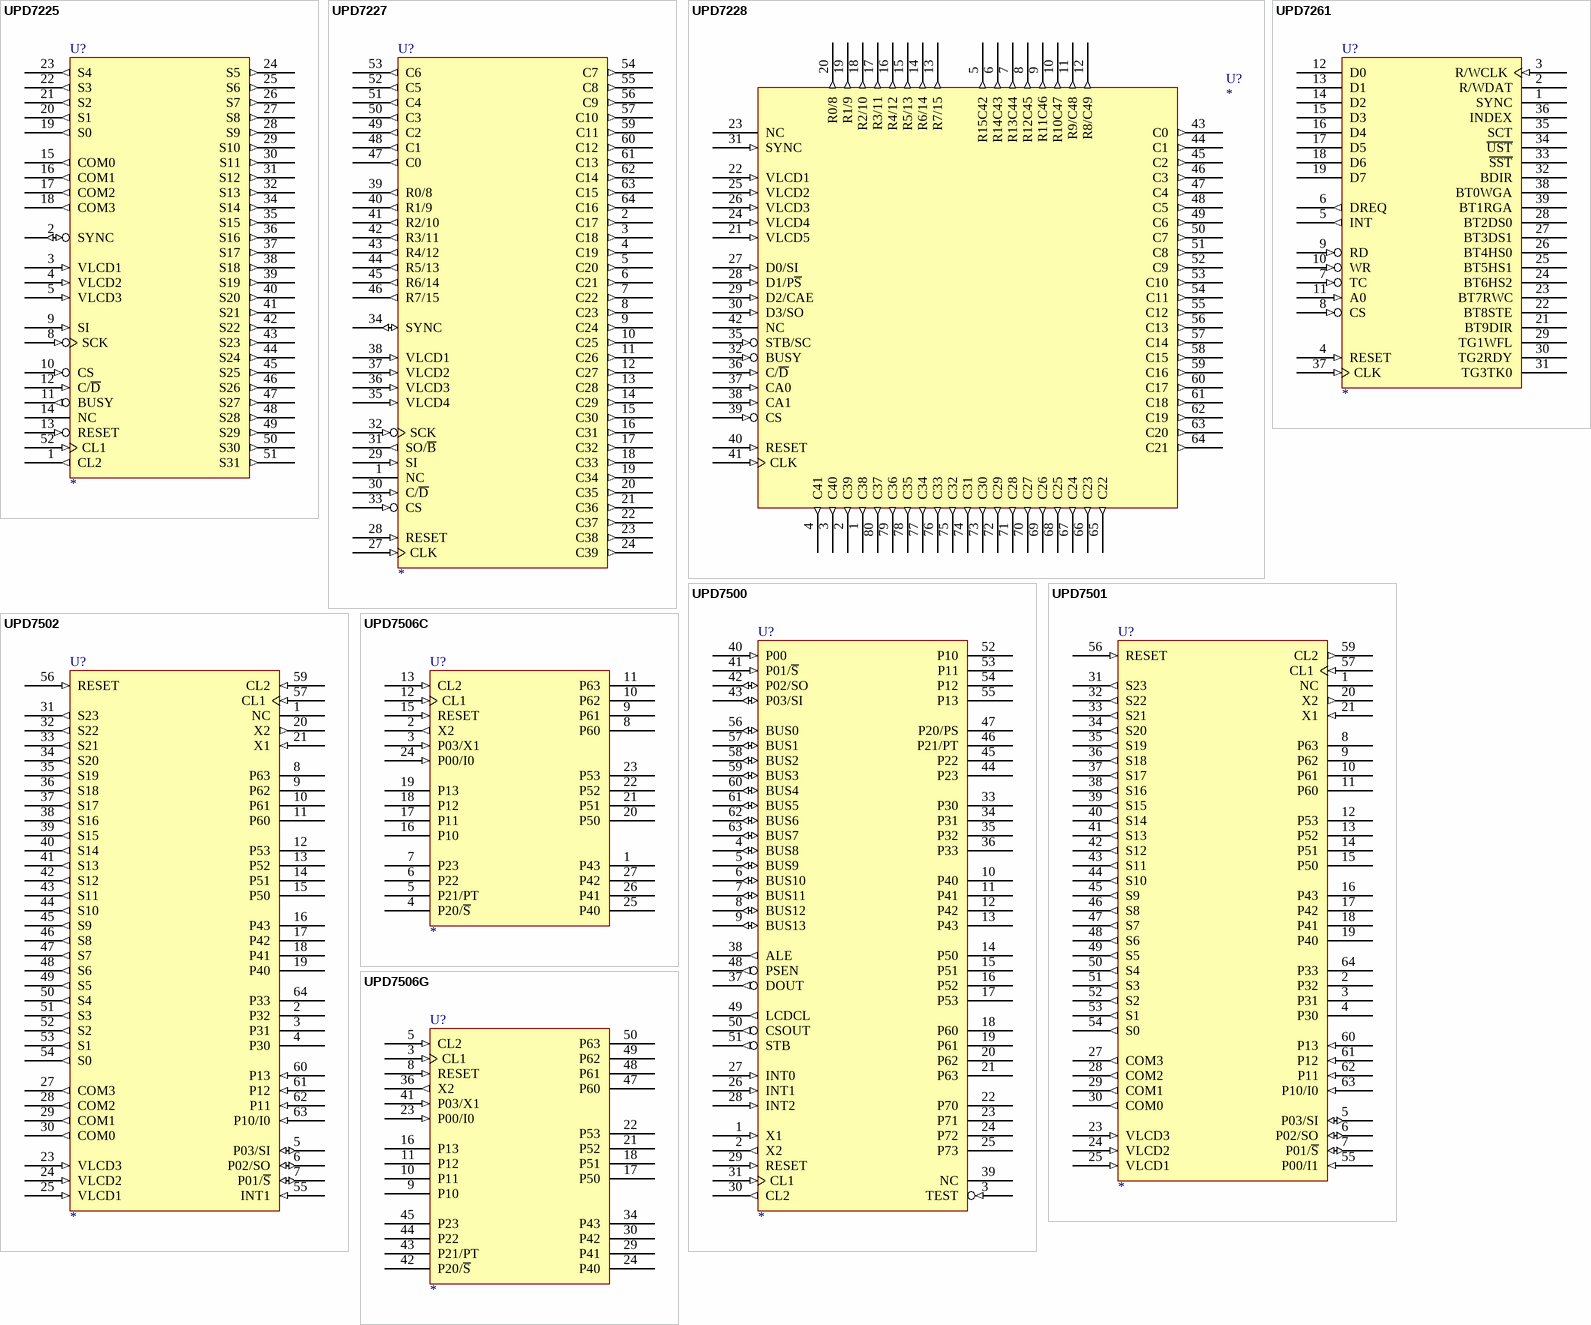
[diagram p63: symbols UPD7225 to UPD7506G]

## UPD7225
designator U?
footprint QFP-52
pins: 1 CL2 (out), 2 SYNC (io), 3 VLCD1 (in), 4 VLCD2 (in), 5 VLCD3 (in), 6 GND (power) hidden to GND, 7 VCC (power) hidden to VCC, 8 SCK (in), 9 SI (in), 10 CS (in), 11 BUSY (out), 12 C/~{D} (in), 13 RESET (in), 14 NC, 15 COM0 (out), 16 COM1 (out), 17 COM2 (out), 18 COM3 (out), 19 S0 (out), 20 S1 (out), 21 S2 (out), 22 S3 (out), 23 S4 (out), 24 S5 (out), 25 S6 (out), 26 S7 (out), 27 S8 (out), 28 S9 (out), 29 S10 (out), 30 S11 (out), 31 S12 (out), 32 S13 (out), 33 VCC (power) hidden to VCC, 34 S14 (out), 35 S15 (out), 36 S16 (out), 37 S17 (out), 38 S18 (out), 39 S19 (out), 40 S20 (out), 41 S21 (out), 42 S22 (out), 43 S23 (out), 44 S24 (out), 45 S25 (out), 46 S26 (out), 47 S27 (out), 48 S28 (out), 49 S29 (out), 50 S30 (out), 51 S31 (out), 52 CL1 (in)
2 alternate drawings of the same symbol

## UPD7227
designator U?
footprint QFP-64
pins: 1 NC, 2 C17 (out), 3 C18 (out), 4 C19 (out), 5 C20 (out), 6 C21 (out), 7 C22 (out), 8 C23 (out), 9 C24 (out), 10 C25 (out), 11 C26 (out), 12 C27 (out), 13 C28 (out), 14 C29 (out), 15 C30 (out), 16 C31 (out), 17 C32 (out), 18 C33 (out), 19 C34 (out), 20 C35 (out), 21 C36 (out), 22 C37 (out), 23 C38 (out), 24 C39 (out), 25 GND (power) hidden to GND, 26 VCC (power) hidden to VCC, 27 CLK (in), 28 RESET (in), 29 SI (in), 30 C/~{D} (in), 31 SO/~{B} (out), 32 SCK (in), 33 CS (in), 34 SYNC (io), 35 VLCD4 (in), 36 VLCD3 (in), 37 VLCD2 (in), 38 VLCD1 (in), 39 R0/8 (out), 40 R1/9 (out), 41 R2/10 (out), 42 R3/11 (out), 43 R4/12 (out), 44 R5/13 (out), 45 R6/14 (out), 46 R7/15 (out), 47 C0 (out), 48 C1 (out), 49 C2 (out), 50 C3 (out), 51 C4 (out), 52 C5 (out), 53 C6 (out), 54 C7 (out), 55 C8 (out), 56 C9 (out), 57 C10 (out), 58 VCC (power) hidden to VCC, 59 C11 (out), 60 C12 (out), 61 C13 (out), 62 C14 (out), 63 C15 (out), 64 C16 (out)
2 alternate drawings of the same symbol

## UPD7228
designator U?
footprint TQFP-80
pins: 1 C38 (out), 2 C39 (out), 3 C40 (out), 4 C41 (out), 5 R15C42 (out), 6 R14C43 (out), 7 R13C44 (out), 8 R12C45 (out), 9 R11C46 (out), 10 R10C47 (out), 11 R9/C48 (out), 12 R8/C49 (out), 13 R7/15 (out), 14 R6/14 (out), 15 R5/13 (out), 16 R4/12 (out), 17 R3/11 (out), 18 R2/10 (out), 19 R1/9 (out), 20 R0/8 (out), 21 VLCD5 (in), 22 VLCD1 (in), 23 NC, 24 VLCD4 (in), 25 VLCD2 (in), 26 VLCD3 (in), 27 D0/SI (in), 28 D1/P~{S} (in), 29 D2/CAE (in), 30 D3/SO (in), 31 SYNC (in), 32 BUSY (in), 33 VCC (power) hidden to VCC, 34 GND (power) hidden to GND, 35 STB/SC (in), 36 C/~{D} (in), 37 CA0 (in), 38 CA1 (in), 39 CS (in), 40 RESET (in), 41 CLK (in), 42 NC, 43 C0 (out), 44 C1 (out), 45 C2 (out), 46 C3 (out), 47 C4 (out), 48 C5 (out), 49 C6 (out), 50 C7 (out), 51 C8 (out), 52 C9 (out), 53 C10 (out), 54 C11 (out), 55 C12 (out), 56 C13 (out), 57 C14 (out), 58 C15 (out), 59 C16 (out), 60 C17 (out), 61 C18 (out), 62 C19 (out), 63 C20 (out), 64 C21 (out), 65 C22 (out), 66 C23 (out), 67 C24 (out), 68 C25 (out), 69 C26 (out), 70 C27 (out), 71 C28 (out), 72 C29 (out), 73 C30 (out), 74 C31 (out), 75 C32 (out), 76 C33 (out), 77 C34 (out), 78 C35 (out), 79 C36 (out), 80 C37 (out)
2 alternate drawings of the same symbol

## UPD7261
designator U?
footprint DIP-40
pins: 1 SYNC (hiz), 2 R/WDAT (hiz), 3 R/WCLK (in), 4 RESET (in), 5 INT (out), 6 DREQ (out), 7 TC (in), 8 CS (in), 9 RD (in), 10 WR (in), 11 A0 (in), 12 D0 (hiz), 13 D1 (hiz), 14 D2 (hiz), 15 D3 (hiz), 16 D4 (hiz), 17 D5 (hiz), 18 D6 (hiz), 19 D7 (hiz), 20 GND (power) hidden to GND, 21 BT9DIR (hiz), 22 BT8STE (hiz), 23 BT7RWC (hiz), 24 BT6HS2 (hiz), 25 BT5HS1 (hiz), 26 BT4HS0 (hiz), 27 BT3DS1 (hiz), 28 BT2DS0 (hiz), 29 TG1WFL (hiz), 30 TG2RDY (hiz), 31 TG3TK0 (hiz), 32 BDIR (hiz), 33 ~{SST} (hiz), 34 ~{UST} (hiz), 35 SCT (hiz), 36 INDEX (hiz), 37 CLK (in), 38 BT0WGA (hiz), 39 BT1RGA (hiz), 40 VCC (power) hidden to VCC
2 alternate drawings of the same symbol

## UPD7500
designator U?
footprint QUIL64
pins: 1 X1 (in), 2 X2 (out), 3 TEST (in), 4 BUS8 (io), 5 BUS9 (io), 6 BUS10 (io), 7 BUS11 (io), 8 BUS12 (io), 9 BUS13 (io), 10 P40 (hiz), 11 P41 (hiz), 12 P42 (hiz), 13 P43 (hiz), 14 P50 (hiz), 15 P51 (hiz), 16 P52 (hiz), 17 P53 (hiz), 18 P60 (hiz), 19 P61 (hiz), 20 P62 (hiz), 21 P63 (hiz), 22 P70 (hiz), 23 P71 (hiz), 24 P72 (hiz), 25 P73 (hiz), 26 INT1 (in), 27 INT0 (in), 28 INT2 (in), 29 RESET (in), 30 CL2 (out), 31 CL1 (in), 32 VCC (power) hidden to VCC, 33 P30 (hiz), 34 P31 (hiz), 35 P32 (hiz), 36 P33 (hiz), 37 DOUT (out), 38 ALE (out), 39 NC, 40 P00 (in), 41 P01/~{S} (in), 42 P02/SO (io), 43 P03/SI (io), 44 P23 (hiz), 45 P22 (hiz), 46 P21/PT (hiz), 47 P20/PS (hiz), 48 PSEN (out), 49 LCDCL (out), 50 CSOUT (out), 51 STB (out), 52 P10 (hiz), 53 P11 (hiz), 54 P12 (hiz), 55 P13 (hiz), 56 BUS0 (io), 57 BUS1 (io), 58 BUS2 (io), 59 BUS3 (io), 60 BUS4 (io), 61 BUS5 (io), 62 BUS6 (io), 63 BUS7 (io), 64 GND (power) hidden to GND
2 alternate drawings of the same symbol

## UPD7501
designator U?
footprint QFP-64
pins: 1 NC, 2 P32 (hiz), 3 P31 (hiz), 4 P30 (hiz), 5 P03/SI (io), 6 P02/SO (io), 7 P01/~{S} (io), 8 P63 (hiz), 9 P62 (hiz), 10 P61 (hiz), 11 P60 (hiz), 12 P53 (hiz), 13 P52 (hiz), 14 P51 (hiz), 15 P50 (hiz), 16 P43 (hiz), 17 P42 (hiz), 18 P41 (hiz), 19 P40 (hiz), 20 X2 (out), 21 X1 (in), 22 GND (power) hidden to GND, 23 VLCD3 (in), 24 VLCD2 (in), 25 VLCD1 (in), 26 VCC (power) hidden to VCC, 27 COM3 (out), 28 COM2 (out), 29 COM1 (out), 30 COM0 (out), 31 S23 (out), 32 S22 (out), 33 S21 (out), 34 S20 (out), 35 S19 (out), 36 S18 (out), 37 S17 (out), 38 S16 (out), 39 S15 (out), 40 S14 (out), 41 S13 (out), 42 S12 (out), 43 S11 (out), 44 S10 (out), 45 S9 (out), 46 S8 (out), 47 S7 (out), 48 S6 (out), 49 S5 (out), 50 S4 (out), 51 S3 (out), 52 S2 (out), 53 S1 (out), 54 S0 (out), 55 P00/I1 (in), 56 RESET (in), 57 CL1 (in), 58 VCC (power) hidden to VCC, 59 CL2 (out), 60 P13 (in), 61 P12 (in), 62 P11 (in), 63 P10/I0 (in), 64 P33 (hiz)
2 alternate drawings of the same symbol

## UPD7502
designator U?
footprint QFP-64
pins: 1 NC, 2 P32 (hiz), 3 P31 (hiz), 4 P30 (hiz), 5 P03/SI (io), 6 P02/SO (io), 7 P01/~{S} (io), 8 P63 (hiz), 9 P62 (hiz), 10 P61 (hiz), 11 P60 (hiz), 12 P53 (hiz), 13 P52 (hiz), 14 P51 (hiz), 15 P50 (hiz), 16 P43 (hiz), 17 P42 (hiz), 18 P41 (hiz), 19 P40 (hiz), 20 X2 (out), 21 X1 (in), 22 GND (power) hidden to GND, 23 VLCD3 (in), 24 VLCD2 (in), 25 VLCD1 (in), 26 VCC (power) hidden to VCC, 27 COM3 (out), 28 COM2 (out), 29 COM1 (out), 30 COM0 (out), 31 S23 (out), 32 S22 (out), 33 S21 (out), 34 S20 (out), 35 S19 (out), 36 S18 (out), 37 S17 (out), 38 S16 (out), 39 S15 (out), 40 S14 (out), 41 S13 (out), 42 S12 (out), 43 S11 (out), 44 S10 (out), 45 S9 (out), 46 S8 (out), 47 S7 (out), 48 S6 (out), 49 S5 (out), 50 S4 (out), 51 S3 (out), 52 S2 (out), 53 S1 (out), 54 S0 (out), 55 INT1 (in), 56 RESET (in), 57 CL1 (in), 58 VCC (power) hidden to VCC, 59 CL2 (in), 60 P13 (in), 61 P12 (in), 62 P11 (in), 63 P10/I0 (in), 64 P33 (hiz)
2 alternate drawings of the same symbol

## UPD7506C
designator U?
footprint DIP-28
pins: 1 P43 (hiz), 2 X2 (out), 3 P03/X1 (in), 4 P20/~{S} (hiz), 5 P21/PT (hiz), 6 P22 (hiz), 7 P23 (hiz), 8 P60 (hiz), 9 P61 (hiz), 10 P62 (hiz), 11 P63 (hiz), 12 CL1 (in), 13 CL2 (in), 14 VCC (power) hidden to VCC, 15 RESET (in), 16 P10 (hiz), 17 P11 (hiz), 18 P12 (hiz), 19 P13 (hiz), 20 P50 (hiz), 21 P51 (hiz), 22 P52 (hiz), 23 P53 (hiz), 24 P00/I0 (in), 25 P40 (hiz), 26 P41 (hiz), 27 P42 (hiz), 28 GND (power) hidden to GND
2 alternate drawings of the same symbol

## UPD7506G
designator U?
footprint QFP-52
pins: 3 CL1 (in), 5 CL2 (in), 7 VCC (power) hidden to VCC, 8 RESET (in), 9 P10 (hiz), 10 P11 (hiz), 11 P12 (hiz), 16 P13 (hiz), 17 P50 (hiz), 18 P51 (hiz), 21 P52 (hiz), 22 P53 (hiz), 23 P00/I0 (in), 24 P40 (hiz), 29 P41 (hiz), 30 P42 (hiz), 31 GND (power) hidden to GND, 33 VCC (power) hidden to VCC, 34 P43 (hiz), 36 X2 (out), 41 P03/X1 (in), 42 P20/~{S} (hiz), 43 P21/PT (hiz), 44 P22 (hiz), 45 P23 (hiz), 47 P60 (hiz), 48 P61 (hiz), 49 P62 (hiz), 50 P63 (hiz)
2 alternate drawings of the same symbol

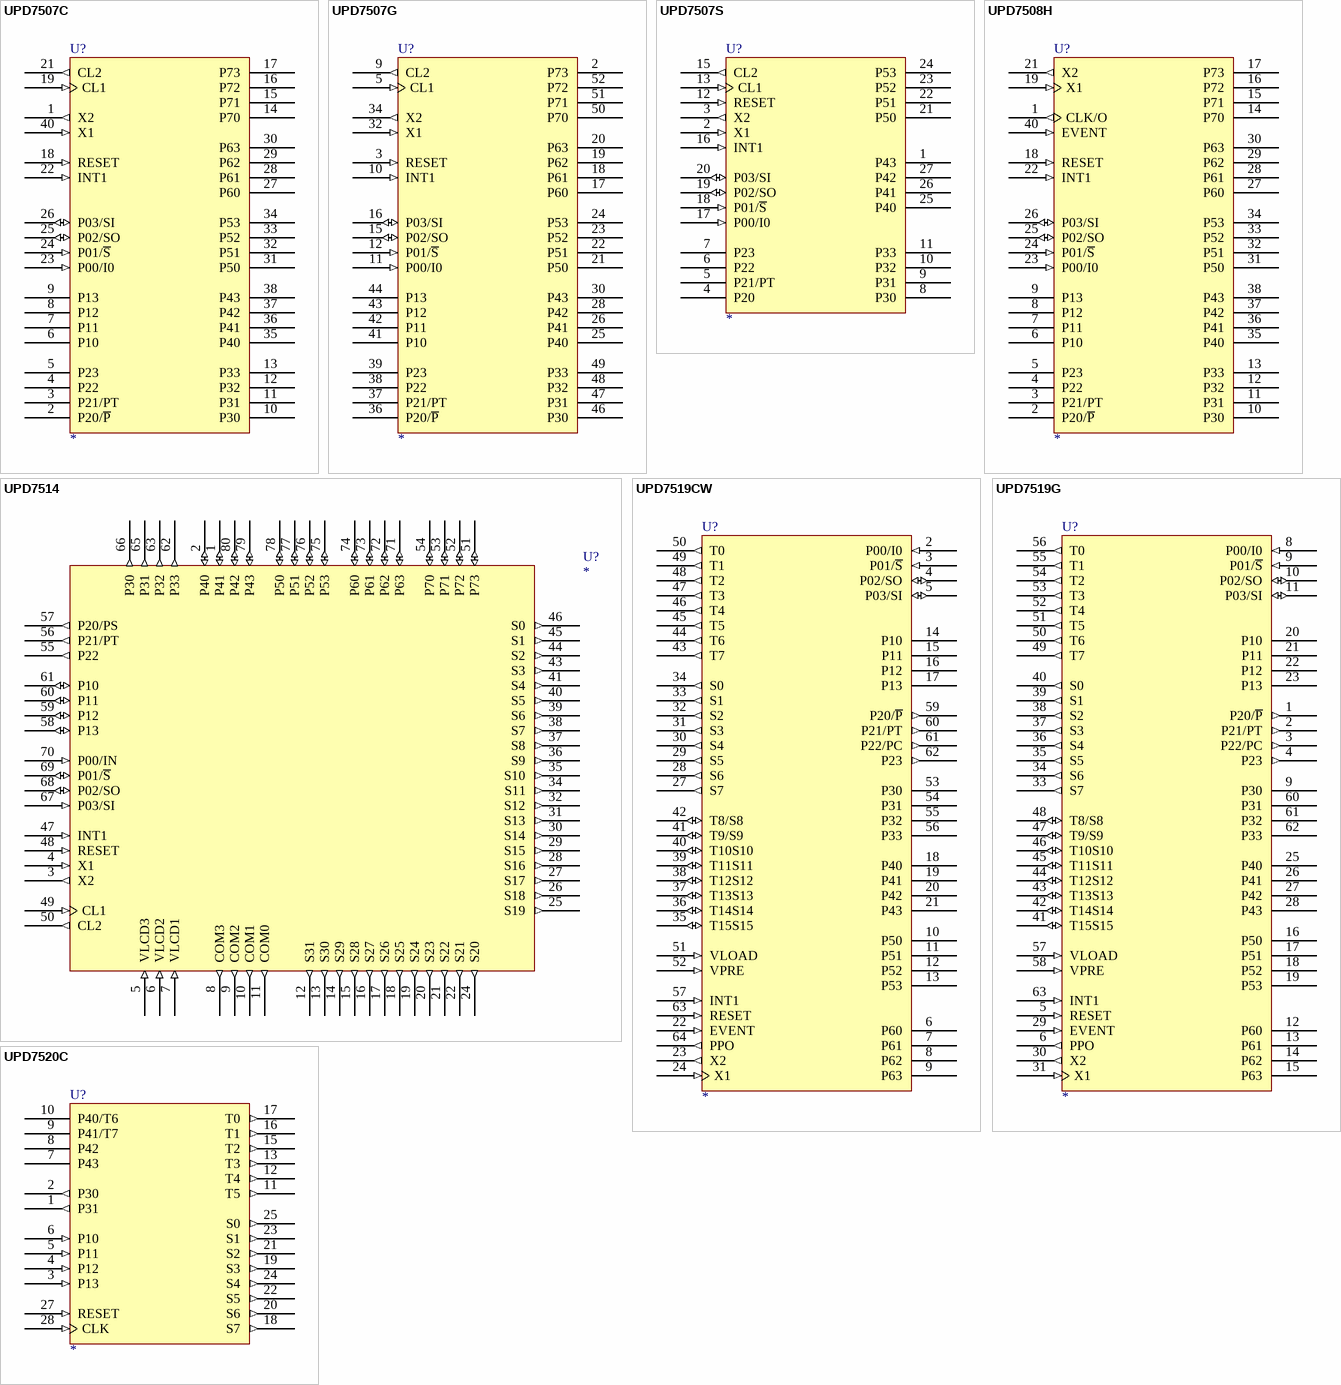
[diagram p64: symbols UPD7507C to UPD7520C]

## UPD7507C
designator U?
footprint DIP-40
pins: 1 X2 (out), 2 P20/~{P} (hiz), 3 P21/PT (hiz), 4 P22 (hiz), 5 P23 (hiz), 6 P10 (hiz), 7 P11 (hiz), 8 P12 (hiz), 9 P13 (hiz), 10 P30 (hiz), 11 P31 (hiz), 12 P32 (hiz), 13 P33 (hiz), 14 P70 (hiz), 15 P71 (hiz), 16 P72 (hiz), 17 P73 (hiz), 18 RESET (in), 19 CL1 (in), 20 VCC (power) hidden to VCC, 21 CL2 (out), 22 INT1 (in), 23 P00/I0 (in), 24 P01/~{S} (in), 25 P02/SO (io), 26 P03/SI (io), 27 P60 (hiz), 28 P61 (hiz), 29 P62 (hiz), 30 P63 (hiz), 31 P50 (hiz), 32 P51 (hiz), 33 P52 (hiz), 34 P53 (hiz), 35 P40 (hiz), 36 P41 (hiz), 37 P42 (hiz), 38 P43 (hiz), 39 GND (power) hidden to GND, 40 X1 (in)
2 alternate drawings of the same symbol

## UPD7507G
designator U?
footprint QFP-52
pins: 2 P73 (hiz), 3 RESET (in), 5 CL1 (in), 7 VCC (power) hidden to VCC, 9 CL2 (out), 10 INT1 (in), 11 P00/I0 (in), 12 P01/~{S} (in), 15 P02/SO (io), 16 P03/SI (io), 17 P60 (hiz), 18 P61 (hiz), 19 P62 (hiz), 20 P63 (hiz), 21 P50 (hiz), 22 P51 (hiz), 23 P52 (hiz), 24 P53 (hiz), 25 P40 (hiz), 26 P41 (hiz), 28 P42 (hiz), 30 P43 (hiz), 31 GND (power) hidden to GND, 32 X1 (in), 33 VCC (power) hidden to VCC, 34 X2 (out), 36 P20/~{P} (hiz), 37 P21/PT (hiz), 38 P22 (hiz), 39 P23 (hiz), 41 P10 (hiz), 42 P11 (hiz), 43 P12 (hiz), 44 P13 (hiz), 46 P30 (hiz), 47 P31 (hiz), 48 P32 (hiz), 49 P33 (hiz), 50 P70 (hiz), 51 P71 (hiz), 52 P72 (hiz)
2 alternate drawings of the same symbol

## UPD7507S
designator U?
footprint DIP-28
pins: 1 P43 (hiz), 2 X1 (in), 3 X2 (out), 4 P20 (hiz), 5 P21/PT (hiz), 6 P22 (hiz), 7 P23 (hiz), 8 P30 (hiz), 9 P31 (hiz), 10 P32 (hiz), 11 P33 (hiz), 12 RESET (in), 13 CL1 (in), 14 VCC (power) hidden to VCC, 15 CL2 (out), 16 INT1 (in), 17 P00/I0 (in), 18 P01/~{S} (in), 19 P02/SO (io), 20 P03/SI (io), 21 P50 (hiz), 22 P51 (hiz), 23 P52 (hiz), 24 P53 (hiz), 25 P40 (hiz), 26 P41 (hiz), 27 P42 (hiz), 28 GND (power) hidden to GND
2 alternate drawings of the same symbol

## UPD7508H
designator U?
footprint DIP-40
pins: 1 CLK/O (out), 2 P20/~{P} (hiz), 3 P21/PT (hiz), 4 P22 (hiz), 5 P23 (hiz), 6 P10 (hiz), 7 P11 (hiz), 8 P12 (hiz), 9 P13 (hiz), 10 P30 (hiz), 11 P31 (hiz), 12 P32 (hiz), 13 P33 (hiz), 14 P70 (hiz), 15 P71 (hiz), 16 P72 (hiz), 17 P73 (hiz), 18 RESET (in), 19 X1 (in), 20 VCC (power) hidden to VCC, 21 X2 (out), 22 INT1 (in), 23 P00/I0 (in), 24 P01/~{S} (in), 25 P02/SO (io), 26 P03/SI (io), 27 P60 (hiz), 28 P61 (hiz), 29 P62 (hiz), 30 P63 (hiz), 31 P50 (hiz), 32 P51 (hiz), 33 P52 (hiz), 34 P53 (hiz), 35 P40 (hiz), 36 P41 (hiz), 37 P42 (hiz), 38 P43 (hiz), 39 VCC (power) hidden to VCC, 40 EVENT (in)
2 alternate drawings of the same symbol

## UPD7514
designator U?
footprint TQFP-80
pins: 1 P41 (io), 2 P40 (io), 3 X2 (out), 4 X1 (in), 5 VLCD3 (in), 6 VLCD2 (in), 7 VLCD1 (in), 8 COM3 (out), 9 COM2 (out), 10 COM1 (out), 11 COM0 (out), 12 S31 (out), 13 S30 (out), 14 S29 (out), 15 S28 (out), 16 S27 (out), 17 S26 (out), 18 S25 (out), 19 S24 (out), 20 S23 (out), 21 S22 (out), 22 S21 (out), 24 S20 (out), 25 S19 (out), 26 S18 (out), 27 S17 (out), 28 S16 (out), 29 S15 (out), 30 S14 (out), 31 S13 (out), 32 S12 (out), 33 VCC (power) hidden to VCC, 34 S11 (out), 35 S10 (out), 36 S9 (out), 37 S8 (out), 38 S7 (out), 39 S6 (out), 40 S5 (out), 41 S4 (out), 43 S3 (out), 44 S2 (out), 45 S1 (out), 46 S0 (out), 47 INT1 (in), 48 RESET (in), 49 CL1 (in), 50 CL2 (out), 51 P73 (io), 52 P72 (io), 53 P71 (io), 54 P70 (io), 55 P22 (out), 56 P21/PT (out), 57 P20/PS (out), 58 P13 (io), 59 P12 (io), 60 P11 (io), 61 P10 (io), 62 P33 (out), 63 P32 (out), 64 GND (power) hidden to GND, 65 P31 (out), 66 P30 (out), 67 P03/SI (in), 68 P02/SO (io), 69 P01/~{S} (io), 70 P00/IN (in), 71 P63 (io), 72 P62 (io), 73 P61 (io), 74 P60 (io), 75 P53 (io), 76 P52 (io), 77 P51 (io), 78 P50 (io), 79 P43 (io), 80 P42 (io)
2 alternate drawings of the same symbol

## UPD7519CW
designator U?
footprint QFP-64
pins: 2 P00/I0 (in), 3 P01/~{S} (in), 4 P02/SO (io), 5 P03/SI (io), 6 P60 (hiz), 7 P61 (hiz), 8 P62 (hiz), 9 P63 (hiz), 10 P50 (hiz), 11 P51 (hiz), 12 P52 (hiz), 13 P53 (hiz), 14 P10 (hiz), 15 P11 (hiz), 16 P12 (hiz), 17 P13 (hiz), 18 P40 (hiz), 19 P41 (hiz), 20 P42 (hiz), 21 P43 (hiz), 22 EVENT (in), 23 X2 (out), 24 X1 (in), 25 GND (power) hidden to GND, 26 VCC (power) hidden to VCC, 27 S7 (out), 28 S6 (out), 29 S5 (out), 30 S4 (out), 31 S3 (out), 32 S2 (out), 33 S1 (out), 34 S0 (out), 35 T15S15 (io), 36 T14S14 (io), 37 T13S13 (io), 38 T12S12 (io), 39 T11S11 (io), 40 T10S10 (io), 41 T9/S9 (io), 42 T8/S8 (io), 43 T7 (out), 44 T6 (out), 45 T5 (out), 46 T4 (out), 47 T3 (out), 48 T2 (out), 49 T1 (out), 50 T0 (out), 51 VLOAD (in), 52 VPRE (in), 53 P30 (hiz), 54 P31 (hiz), 55 P32 (hiz), 56 P33 (hiz), 57 INT1 (in), 58 VCC (power) hidden to VCC, 59 P20/~{P} (out), 60 P21/PT (out), 61 P22/PC (out), 62 P23 (out), 63 RESET (in), 64 PPO (out)
2 alternate drawings of the same symbol

## UPD7519G
designator U?
footprint QUIL64
pins: 1 P20/~{P} (out), 2 P21/PT (out), 3 P22/PC (out), 4 P23 (out), 5 RESET (in), 6 PPO (out), 8 P00/I0 (in), 9 P01/~{S} (in), 9 P30 (hiz), 10 P02/SO (io), 11 P03/SI (io), 12 P60 (hiz), 13 P61 (hiz), 14 P62 (hiz), 15 P63 (hiz), 16 P50 (hiz), 17 P51 (hiz), 18 P52 (hiz), 19 P53 (hiz), 20 P10 (hiz), 21 P11 (hiz), 22 P12 (hiz), 23 P13 (hiz), 25 P40 (hiz), 26 P41 (hiz), 27 P42 (hiz), 28 P43 (hiz), 29 EVENT (in), 30 X2 (out), 31 X1 (in), 32 GND (power) hidden to GND, 33 S7 (out), 34 S6 (out), 35 S5 (out), 36 S4 (out), 37 S3 (out), 38 S2 (out), 39 S1 (out), 40 S0 (out), 41 T15S15 (io), 42 T14S14 (io), 43 T13S13 (io), 44 T12S12 (io), 45 T11S11 (io), 46 T10S10 (io), 47 T9/S9 (io), 48 T8/S8 (io), 49 T7 (out), 50 T6 (out), 51 T5 (out), 52 T4 (out), 53 T3 (out), 54 T2 (out), 55 T1 (out), 56 T0 (out), 57 VLOAD (in), 58 VPRE (in), 60 P31 (hiz), 61 P32 (hiz), 62 P33 (hiz), 63 INT1 (in), 64 VCC (power) hidden to VCC
2 alternate drawings of the same symbol

## UPD7520C
designator U?
footprint DIP-28
pins: 1 P31 (out), 2 P30 (out), 3 P13 (in), 4 P12 (in), 5 P11 (in), 6 P10 (in), 7 P43 (hiz), 8 P42 (hiz), 9 P41/T7 (hiz), 10 P40/T6 (hiz), 11 T5 (out), 12 T4 (out), 13 T3 (out), 14 VCC (power) hidden to VCC, 15 T2 (out), 16 T1 (out), 17 T0 (out), 18 S7 (out), 19 S3 (out), 20 S6 (out), 21 S2 (out), 22 S5 (out), 23 S1 (out), 24 S4 (out), 25 S0 (out), 26 GND (power) hidden to GND, 27 RESET (in), 28 CLK (in)
2 alternate drawings of the same symbol

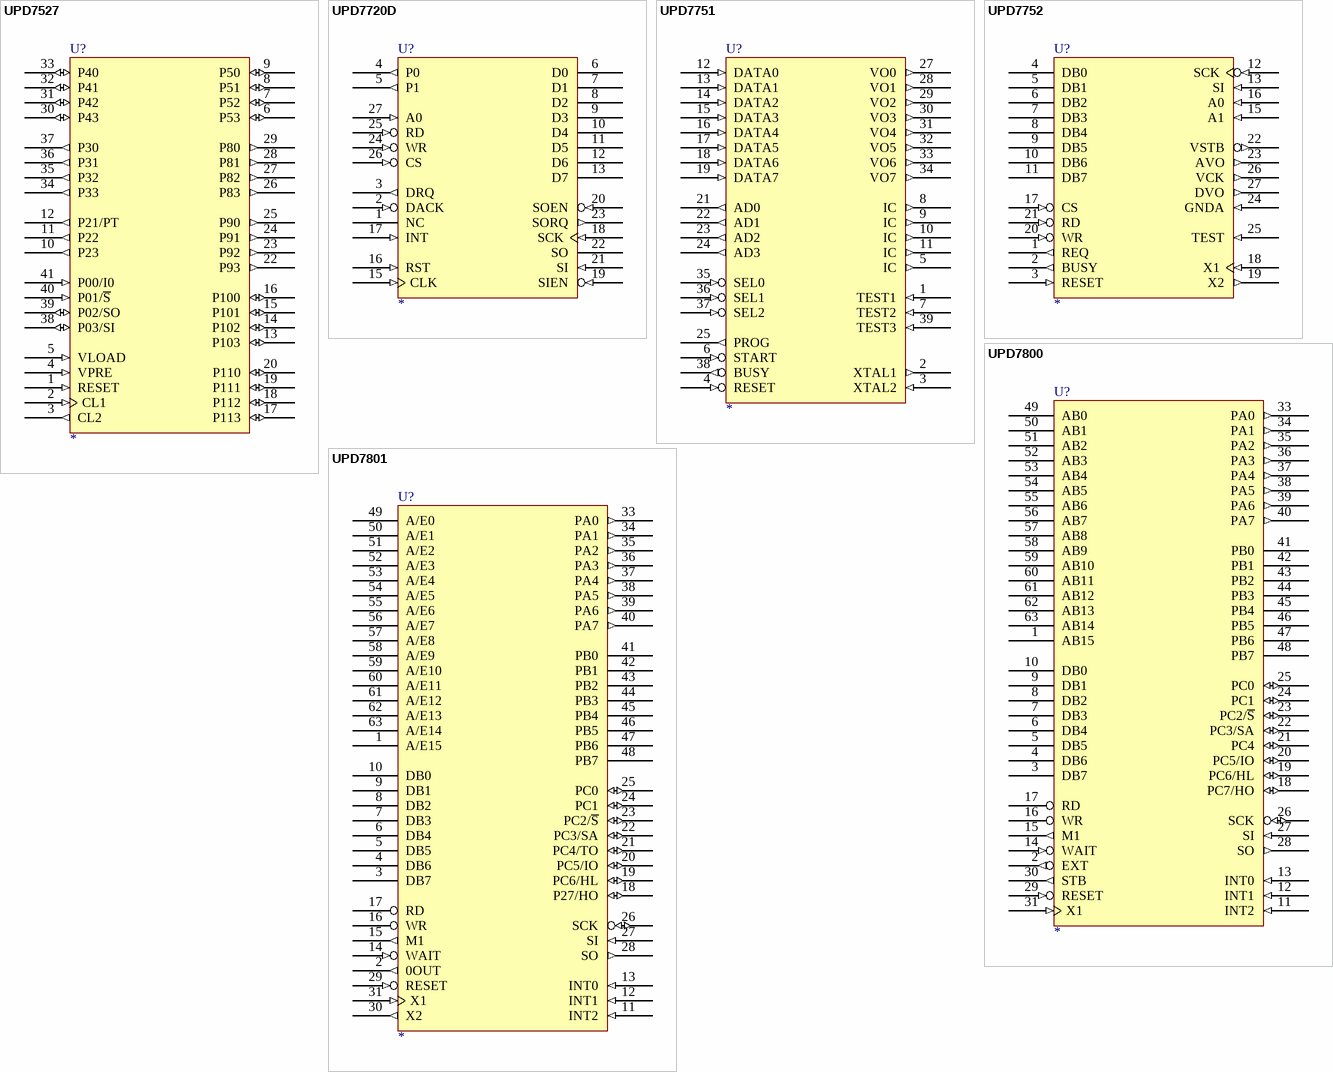
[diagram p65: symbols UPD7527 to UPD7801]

## UPD7527
designator U?
footprint DIP42
pins: 1 RESET (in), 2 CL1 (in), 3 CL2 (out), 4 VPRE (in), 5 VLOAD (in), 6 P53 (io), 7 P52 (io), 8 P51 (io), 9 P50 (io), 10 P23 (out), 11 P22 (out), 12 P21/PT (out), 13 P103 (io), 14 P102 (io), 15 P101 (io), 16 P100 (io), 17 P113 (io), 18 P112 (io), 19 P111 (io), 20 P110 (io), 21 VCC (power) hidden to VCC, 22 P93 (out), 23 P92 (out), 24 P91 (out), 25 P90 (out), 26 P83 (out), 27 P82 (out), 28 P81 (out), 29 P80 (out), 30 P43 (io), 31 P42 (io), 32 P41 (io), 33 P40 (io), 34 P33 (out), 35 P32 (out), 36 P31 (out), 37 P30 (out), 38 P03/SI (io), 39 P02/SO (io), 40 P01/~{S} (in), 41 P00/I0 (in), 42 GND (power) hidden to GND
2 alternate drawings of the same symbol

## UPD7720D
designator U?
footprint DIP-40
pins: 1 NC, 2 DACK (in), 3 DRQ (out), 4 P0 (out), 5 P1 (out), 6 D0 (hiz), 7 D1 (hiz), 8 D2 (hiz), 9 D3 (hiz), 10 D4 (hiz), 11 D5 (hiz), 12 D6 (hiz), 13 D7 (hiz), 14 GND (power) hidden to GND, 15 CLK (in), 16 RST (in), 17 INT (in), 18 SCK (in), 19 SIEN (in), 20 SOEN (in), 21 SI (in), 22 SO (hiz), 23 SORQ (out), 24 WR (in), 25 RD (in), 26 CS (in), 27 A0 (in), 28 VCC (power) hidden to VCC
2 alternate drawings of the same symbol

## UPD7751
designator U?
footprint DIP-40
pins: 1 TEST1 (in), 2 XTAL1 (out), 3 XTAL2 (in), 4 RESET (in), 5 IC (out), 6 START (in), 7 TEST2 (in), 8 IC (out), 9 IC (out), 10 IC (out), 11 IC (out), 12 DATA0 (in), 13 DATA1 (in), 14 DATA2 (in), 15 DATA3 (in), 16 DATA4 (in), 17 DATA5 (in), 18 DATA6 (in), 19 DATA7 (in), 20 GND (power) hidden to GND, 21 AD0 (out), 22 AD1 (out), 23 AD2 (out), 24 AD3 (out), 25 PROG (out), 26 VCC (power) hidden to VCC, 27 VO0 (out), 28 VO1 (out), 29 VO2 (out), 30 VO3 (out), 31 VO4 (out), 32 VO5 (out), 33 VO6 (out), 34 VO7 (out), 35 SEL0 (in), 36 SEL1 (in), 37 SEL2 (in), 38 BUSY (out), 39 TEST3 (in), 40 VCC (power) hidden to VCC
2 alternate drawings of the same symbol

## UPD7752
designator U?
footprint DIP-28
pins: 1 REQ (out), 2 BUSY (out), 3 RESET (in), 4 DB0 (hiz), 5 DB1 (hiz), 6 DB2 (hiz), 7 DB3 (hiz), 8 DB4 (hiz), 9 DB5 (hiz), 10 DB6 (hiz), 11 DB7 (hiz), 12 SCK (in), 13 SI (in), 14 GND (power) hidden to GND, 15 A1 (in), 16 A0 (in), 17 CS (in), 18 X1 (in), 19 X2 (out), 20 WR (in), 21 RD (in), 22 VSTB (out), 23 AVO (out), 24 GNDA (in), 25 TEST (in), 26 VCK (out), 27 DVO (out), 28 VCC (power) hidden to VCC
2 alternate drawings of the same symbol

## UPD7800
designator U?
footprint QUIL64
pins: 1 AB15 (hiz), 2 EXT (out), 3 DB7 (hiz), 4 DB6 (hiz), 5 DB5 (hiz), 6 DB4 (hiz), 7 DB3 (hiz), 8 DB2 (hiz), 9 DB1 (hiz), 10 DB0 (hiz), 11 INT2 (in), 12 INT1 (in), 13 INT0 (in), 14 WAIT (in), 15 M1 (out), 16 WR (hiz), 17 RD (hiz), 18 PC7/HO (io), 19 PC6/HL (io), 20 PC5/IO (io), 21 PC4 (io), 22 PC3/SA (io), 23 PC2/~{S} (io), 24 PC1 (io), 25 PC0 (io), 26 SCK (io), 27 SI (in), 28 SO (out), 29 RESET (in), 30 STB (out), 31 X1 (in), 32 GND (power) hidden to GND, 33 PA0 (out), 34 PA1 (out), 35 PA2 (out), 36 PA3 (out), 37 PA4 (out), 38 PA5 (out), 39 PA6 (out), 40 PA7 (out), 41 PB0 (hiz), 42 PB1 (hiz), 43 PB2 (hiz), 44 PB3 (hiz), 45 PB4 (hiz), 46 PB5 (hiz), 47 PB6 (hiz), 48 PB7 (hiz), 49 AB0 (hiz), 50 AB1 (hiz), 51 AB2 (hiz), 52 AB3 (hiz), 53 AB4 (hiz), 54 AB5 (hiz), 55 AB6 (hiz), 56 AB7 (hiz), 57 AB8 (hiz), 58 AB9 (hiz), 59 AB10 (hiz), 60 AB11 (hiz), 61 AB12 (hiz), 62 AB13 (hiz), 63 AB14 (hiz), 64 VCC (power) hidden to VCC
2 alternate drawings of the same symbol

## UPD7801
designator U?
footprint QUIL64
pins: 1 A/E15 (hiz), 2 0OUT (out), 3 DB7 (hiz), 4 DB6 (hiz), 5 DB5 (hiz), 6 DB4 (hiz), 7 DB3 (hiz), 8 DB2 (hiz), 9 DB1 (hiz), 10 DB0 (hiz), 11 INT2 (in), 12 INT1 (in), 13 INT0 (in), 14 WAIT (in), 15 M1 (out), 16 WR (hiz), 17 RD (hiz), 18 P27/HO (io), 19 PC6/HL (io), 20 PC5/IO (io), 21 PC4/TO (io), 22 PC3/SA (io), 23 PC2/~{S} (io), 24 PC1 (io), 25 PC0 (io), 26 SCK (io), 27 SI (in), 28 SO (out), 29 RESET (in), 30 X2 (out), 31 X1 (in), 32 GND (power) hidden to GND, 33 PA0 (out), 34 PA1 (out), 35 PA2 (out), 36 PA3 (out), 37 PA4 (out), 38 PA5 (out), 39 PA6 (out), 40 PA7 (out), 41 PB0 (hiz), 42 PB1 (hiz), 43 PB2 (hiz), 44 PB3 (hiz), 45 PB4 (hiz), 46 PB5 (hiz), 47 PB6 (hiz), 48 PB7 (hiz), 49 A/E0 (hiz), 50 A/E1 (hiz), 51 A/E2 (hiz), 52 A/E3 (hiz), 53 A/E4 (hiz), 54 A/E5 (hiz), 55 A/E6 (hiz), 56 A/E7 (hiz), 57 A/E8 (hiz), 58 A/E9 (hiz), 59 A/E10 (hiz), 60 A/E11 (hiz), 61 A/E12 (hiz), 62 A/E13 (hiz), 63 A/E14 (hiz), 64 VCC (power) hidden to VCC
2 alternate drawings of the same symbol

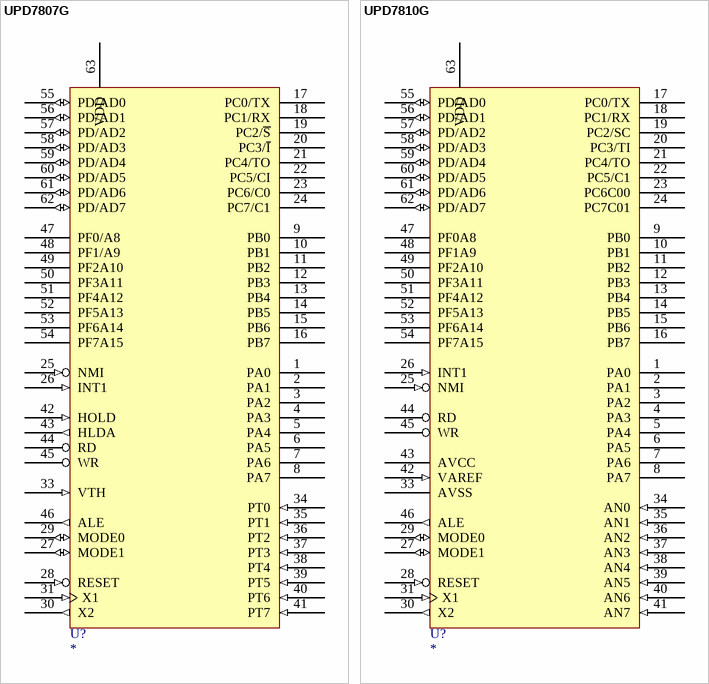
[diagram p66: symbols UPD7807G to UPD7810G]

## UPD7807G
designator U?
footprint QUIL64
pins: 1 PA0 (hiz), 2 PA1 (hiz), 3 PA2 (hiz), 4 PA3 (hiz), 5 PA4 (hiz), 6 PA5 (hiz), 7 PA6 (hiz), 8 PA7 (hiz), 9 PB0 (hiz), 10 PB1 (hiz), 11 PB2 (hiz), 12 PB3 (hiz), 13 PB4 (hiz), 14 PB5 (hiz), 15 PB6 (hiz), 16 PB7 (hiz), 17 PC0/TX (hiz), 18 PC1/RX (hiz), 19 PC2/~{S} (hiz), 20 PC3/~{I} (hiz), 21 PC4/TO (hiz), 22 PC5/CI (hiz), 23 PC6/C0 (hiz), 24 PC7/C1 (hiz), 25 NMI (in), 26 INT1 (in), 27 MODE1 (io), 28 RESET (in), 29 MODE0 (io), 30 X2 (out), 31 X1 (in), 32 GND (power) hidden to GND, 33 VTH (in), 34 PT0 (in), 35 PT1 (in), 36 PT2 (in), 37 PT3 (in), 38 PT4 (in), 39 PT5 (in), 40 PT6 (in), 41 PT7 (in), 42 HOLD (in), 43 HLDA (out), 44 RD (hiz), 45 WR (hiz), 46 ALE (out), 47 PF0/A8 (hiz), 48 PF1/A9 (hiz), 49 PF2A10 (hiz), 50 PF3A11 (hiz), 51 PF4A12 (hiz), 52 PF5A13 (hiz), 53 PF6A14 (hiz), 54 PF7A15 (hiz), 55 PD/AD0 (io), 56 PD/AD1 (io), 57 PD/AD2 (io), 58 PD/AD3 (io), 59 PD/AD4 (io), 60 PD/AD5 (io), 61 PD/AD6 (io), 62 PD/AD7 (io), 63 VDD (power), 64 VCC (power) hidden to VCC
2 alternate drawings of the same symbol

## UPD7810G
designator U?
footprint QUIL64
pins: 1 PA0 (hiz), 2 PA1 (hiz), 3 PA2 (hiz), 4 PA3 (hiz), 5 PA4 (hiz), 6 PA5 (hiz), 7 PA6 (hiz), 8 PA7 (hiz), 9 PB0 (hiz), 10 PB1 (hiz), 11 PB2 (hiz), 12 PB3 (hiz), 13 PB4 (hiz), 14 PB5 (hiz), 15 PB6 (hiz), 16 PB7 (hiz), 17 PC0/TX (hiz), 18 PC1/RX (hiz), 19 PC2/SC (hiz), 20 PC3/TI (hiz), 21 PC4/TO (hiz), 22 PC5/C1 (hiz), 23 PC6C00 (hiz), 24 PC7C01 (hiz), 25 NMI (in), 26 INT1 (in), 27 MODE1 (io), 28 RESET (in), 29 MODE0 (io), 30 X2 (out), 31 X1 (in), 32 GND (power) hidden to GND, 33 AVSS (power), 34 AN0 (in), 35 AN1 (in), 36 AN2 (in), 37 AN3 (in), 38 AN4 (in), 39 AN5 (in), 40 AN6 (in), 41 AN7 (in), 42 VAREF (in), 43 AVCC (power), 44 RD (hiz), 45 WR (hiz), 46 ALE (out), 47 PF0A8 (hiz), 48 PF1A9 (hiz), 49 PF2A10 (hiz), 50 PF3A11 (hiz), 51 PF4A12 (hiz), 52 PF5A13 (hiz), 53 PF6A14 (hiz), 54 PF7A15 (hiz), 55 PD/AD0 (io), 56 PD/AD1 (io), 57 PD/AD2 (io), 58 PD/AD3 (io), 59 PD/AD4 (io), 60 PD/AD5 (io), 61 PD/AD6 (io), 62 PD/AD7 (io), 63 VDD (power), 64 VCC (power) hidden to VCC
2 alternate drawings of the same symbol


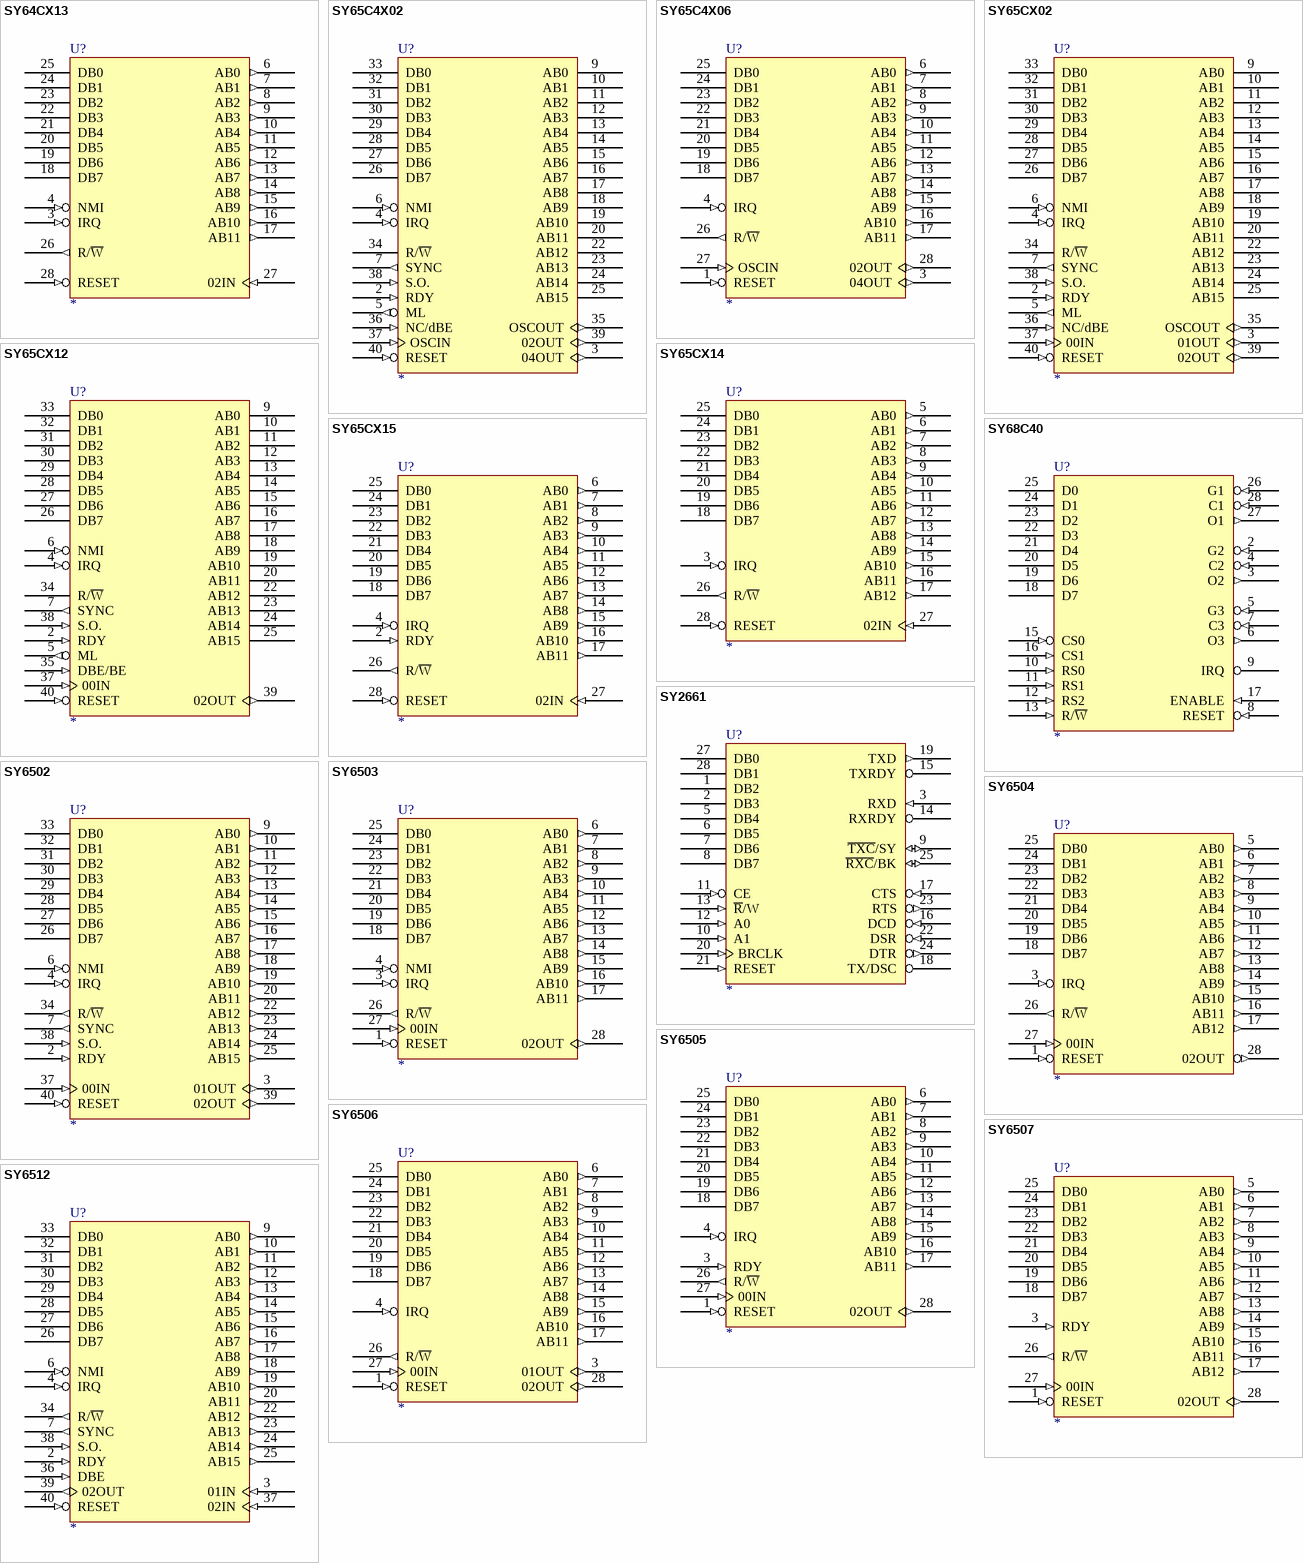
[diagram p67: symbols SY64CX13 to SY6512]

## SY64CX13
designator U?
footprint DIP-28
pins: 1 GND (power) hidden to GND, 3 IRQ (in), 4 NMI (in), 5 VCC (power) hidden to VCC, 6 AB0 (out), 7 AB1 (out), 8 AB2 (out), 9 AB3 (out), 10 AB4 (out), 11 AB5 (out), 12 AB6 (out), 13 AB7 (out), 14 AB8 (out), 15 AB9 (out), 16 AB10 (out), 17 AB11 (out), 18 DB7 (hiz), 19 DB6 (hiz), 20 DB5 (hiz), 21 DB4 (hiz), 22 DB3 (hiz), 23 DB2 (hiz), 24 DB1 (hiz), 25 DB0 (hiz), 26 R/~{W} (out), 27 02IN (in), 28 RESET (in)
2 alternate drawings of the same symbol

## SY65C4X02
designator U?
footprint DIP-40
pins: 1 GND (power) hidden to GND, 2 RDY (in), 3 04OUT (out), 4 IRQ (in), 5 ML (out), 6 NMI (in), 7 SYNC (out), 8 VCC (power) hidden to VCC, 9 AB0 (hiz), 10 AB1 (hiz), 11 AB2 (hiz), 12 AB3 (hiz), 13 AB4 (hiz), 14 AB5 (hiz), 15 AB6 (hiz), 16 AB7 (hiz), 17 AB8 (hiz), 18 AB9 (hiz), 19 AB10 (hiz), 20 AB11 (hiz), 21 GND (power) hidden to GND, 22 AB12 (hiz), 23 AB13 (hiz), 24 AB14 (hiz), 25 AB15 (hiz), 26 DB7 (hiz), 27 DB6 (hiz), 28 DB5 (hiz), 29 DB4 (hiz), 30 DB3 (hiz), 31 DB2 (hiz), 32 DB1 (hiz), 33 DB0 (hiz), 34 R/~{W} (hiz), 35 OSCOUT (out), 36 NC/dBE (in), 37 OSCIN (in), 38 S.O. (in), 39 02OUT (out), 40 RESET (in)
2 alternate drawings of the same symbol

## SY65C4X06
designator U?
footprint DIP-28
pins: 1 RESET (in), 2 GND (power) hidden to GND, 3 04OUT (out), 4 IRQ (in), 5 VCC (power) hidden to VCC, 6 AB0 (out), 7 AB1 (out), 8 AB2 (out), 9 AB3 (out), 10 AB4 (out), 11 AB5 (out), 12 AB6 (out), 13 AB7 (out), 14 AB8 (out), 15 AB9 (out), 16 AB10 (out), 17 AB11 (out), 18 DB7 (hiz), 19 DB6 (hiz), 20 DB5 (hiz), 21 DB4 (hiz), 22 DB3 (hiz), 23 DB2 (hiz), 24 DB1 (hiz), 25 DB0 (hiz), 26 R/~{W} (out), 27 OSCIN (in), 28 02OUT (out)
2 alternate drawings of the same symbol

## SY65CX02
designator U?
footprint DIP-40
pins: 1 GND (power) hidden to GND, 2 RDY (in), 3 01OUT (out), 4 IRQ (in), 5 ML (out), 6 NMI (in), 7 SYNC (out), 8 VCC (power) hidden to VCC, 9 AB0 (hiz), 10 AB1 (hiz), 11 AB2 (hiz), 12 AB3 (hiz), 13 AB4 (hiz), 14 AB5 (hiz), 15 AB6 (hiz), 16 AB7 (hiz), 17 AB8 (hiz), 18 AB9 (hiz), 19 AB10 (hiz), 20 AB11 (hiz), 21 GND (power) hidden to GND, 22 AB12 (hiz), 23 AB13 (hiz), 24 AB14 (hiz), 25 AB15 (hiz), 26 DB7 (hiz), 27 DB6 (hiz), 28 DB5 (hiz), 29 DB4 (hiz), 30 DB3 (hiz), 31 DB2 (hiz), 32 DB1 (hiz), 33 DB0 (hiz), 34 R/~{W} (hiz), 35 OSCOUT (out), 36 NC/dBE (in), 37 00IN (in), 38 S.O. (in), 39 02OUT (out), 40 RESET (in)
2 alternate drawings of the same symbol

## SY65CX12
designator U?
footprint DIP-40
pins: 1 GND (power) hidden to GND, 2 RDY (in), 4 IRQ (in), 5 ML (out), 6 NMI (in), 7 SYNC (out), 8 VCC (power) hidden to VCC, 9 AB0 (hiz), 10 AB1 (hiz), 11 AB2 (hiz), 12 AB3 (hiz), 13 AB4 (hiz), 14 AB5 (hiz), 15 AB6 (hiz), 16 AB7 (hiz), 17 AB8 (hiz), 18 AB9 (hiz), 19 AB10 (hiz), 20 AB11 (hiz), 21 GND (power) hidden to GND, 22 AB12 (hiz), 23 AB13 (hiz), 24 AB14 (hiz), 25 AB15 (hiz), 26 DB7 (hiz), 27 DB6 (hiz), 28 DB5 (hiz), 29 DB4 (hiz), 30 DB3 (hiz), 31 DB2 (hiz), 32 DB1 (hiz), 33 DB0 (hiz), 34 R/~{W} (hiz), 35 DBE/BE (in), 37 00IN (in), 38 S.O. (in), 39 02OUT (out), 40 RESET (in)
2 alternate drawings of the same symbol

## SY65CX14
designator U?
footprint DIP-28
pins: 1 GND (power) hidden to GND, 3 IRQ (in), 4 VCC (power) hidden to VCC, 5 AB0 (out), 6 AB1 (out), 7 AB2 (out), 8 AB3 (out), 9 AB4 (out), 10 AB5 (out), 11 AB6 (out), 12 AB7 (out), 13 AB8 (out), 14 AB9 (out), 15 AB10 (out), 16 AB11 (out), 17 AB12 (out), 18 DB7 (hiz), 19 DB6 (hiz), 20 DB5 (hiz), 21 DB4 (hiz), 22 DB3 (hiz), 23 DB2 (hiz), 24 DB1 (hiz), 25 DB0 (hiz), 26 R/~{W} (out), 27 02IN (in), 28 RESET (in)
2 alternate drawings of the same symbol

## SY65CX15
designator U?
footprint DIP-28
pins: 1 GND (power) hidden to GND, 2 RDY (in), 4 IRQ (in), 5 VCC (power) hidden to VCC, 6 AB0 (out), 7 AB1 (out), 8 AB2 (out), 9 AB3 (out), 10 AB4 (out), 11 AB5 (out), 12 AB6 (out), 13 AB7 (out), 14 AB8 (out), 15 AB9 (out), 16 AB10 (out), 17 AB11 (out), 18 DB7 (hiz), 19 DB6 (hiz), 20 DB5 (hiz), 21 DB4 (hiz), 22 DB3 (hiz), 23 DB2 (hiz), 24 DB1 (hiz), 25 DB0 (hiz), 26 R/~{W} (out), 27 02IN (in), 28 RESET (in)
2 alternate drawings of the same symbol

## SY68C40
designator U?
footprint DIP-28
pins: 1 GND (power) hidden to GND, 2 G2 (in), 3 O2 (out), 4 C2 (in), 5 G3 (in), 6 O3 (out), 7 C3 (in), 8 RESET (in), 9 IRQ (oc), 10 RS0 (in), 11 RS1 (in), 12 RS2 (in), 13 R/~{W} (in), 14 VCC (power) hidden to VCC, 15 CS0 (in), 16 CS1 (in), 17 ENABLE (in), 18 D7 (hiz), 19 D6 (hiz), 20 D5 (hiz), 21 D4 (hiz), 22 D3 (hiz), 23 D2 (hiz), 24 D1 (hiz), 25 D0 (hiz), 26 G1 (in), 27 O1 (out), 28 C1 (in)
2 alternate drawings of the same symbol

## SY2661
designator U?
footprint DIP-28
pins: 1 DB2 (hiz), 2 DB3 (hiz), 3 RXD (in), 4 GND (power) hidden to GND, 5 DB4 (hiz), 6 DB5 (hiz), 7 DB6 (hiz), 8 DB7 (hiz), 9 ~{TXC}/SY (io), 10 A1 (in), 11 CE (in), 12 A0 (in), 13 ~{R}/W (in), 14 RXRDY (oc), 15 TXRDY (oc), 16 DCD (in), 17 CTS (in), 18 TX/DSC (oc), 19 TXD (out), 20 BRCLK (in), 21 RESET (in), 22 DSR (in), 23 RTS (out), 24 DTR (out), 25 ~{RXC}/BK (io), 26 VCC (power) hidden to VCC, 27 DB0 (hiz), 28 DB1 (hiz)
2 alternate drawings of the same symbol

## SY6502
designator U?
footprint DIP-40
pins: 1 GND (power) hidden to GND, 2 RDY (in), 3 01OUT (out), 4 IRQ (in), 6 NMI (in), 7 SYNC (out), 8 VCC (power) hidden to VCC, 9 AB0 (out), 10 AB1 (out), 11 AB2 (out), 12 AB3 (out), 13 AB4 (out), 14 AB5 (out), 15 AB6 (out), 16 AB7 (out), 17 AB8 (out), 18 AB9 (out), 19 AB10 (out), 20 AB11 (out), 21 GND (power) hidden to GND, 22 AB12 (out), 23 AB13 (out), 24 AB14 (out), 25 AB15 (out), 26 DB7 (hiz), 27 DB6 (hiz), 28 DB5 (hiz), 29 DB4 (hiz), 30 DB3 (hiz), 31 DB2 (hiz), 32 DB1 (hiz), 33 DB0 (hiz), 34 R/~{W} (out), 37 00IN (in), 38 S.O. (in), 39 02OUT (out), 40 RESET (in)
2 alternate drawings of the same symbol

## SY6503
designator U?
footprint DIP-28
pins: 1 RESET (in), 2 GND (power) hidden to GND, 3 IRQ (in), 4 NMI (in), 5 VCC (power) hidden to VCC, 6 AB0 (out), 7 AB1 (out), 8 AB2 (out), 9 AB3 (out), 10 AB4 (out), 11 AB5 (out), 12 AB6 (out), 13 AB7 (out), 14 AB8 (out), 15 AB9 (out), 16 AB10 (out), 17 AB11 (out), 18 DB7 (hiz), 19 DB6 (hiz), 20 DB5 (hiz), 21 DB4 (hiz), 22 DB3 (hiz), 23 DB2 (hiz), 24 DB1 (hiz), 25 DB0 (hiz), 26 R/~{W} (out), 27 00IN (in), 28 02OUT (out)
2 alternate drawings of the same symbol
